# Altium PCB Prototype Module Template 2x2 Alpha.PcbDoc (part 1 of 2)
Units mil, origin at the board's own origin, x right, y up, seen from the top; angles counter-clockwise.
Board outline 1561.03 x 1620.2 mil, 6 copper layers (Component Side, Ground Plane (GND), Inner Layer 1, Inner Layer 2, Power Plane (VCC), Solder Side), stack 51.068 mil thick; 166 components, 80 nets, 785 pads, 445 vias.
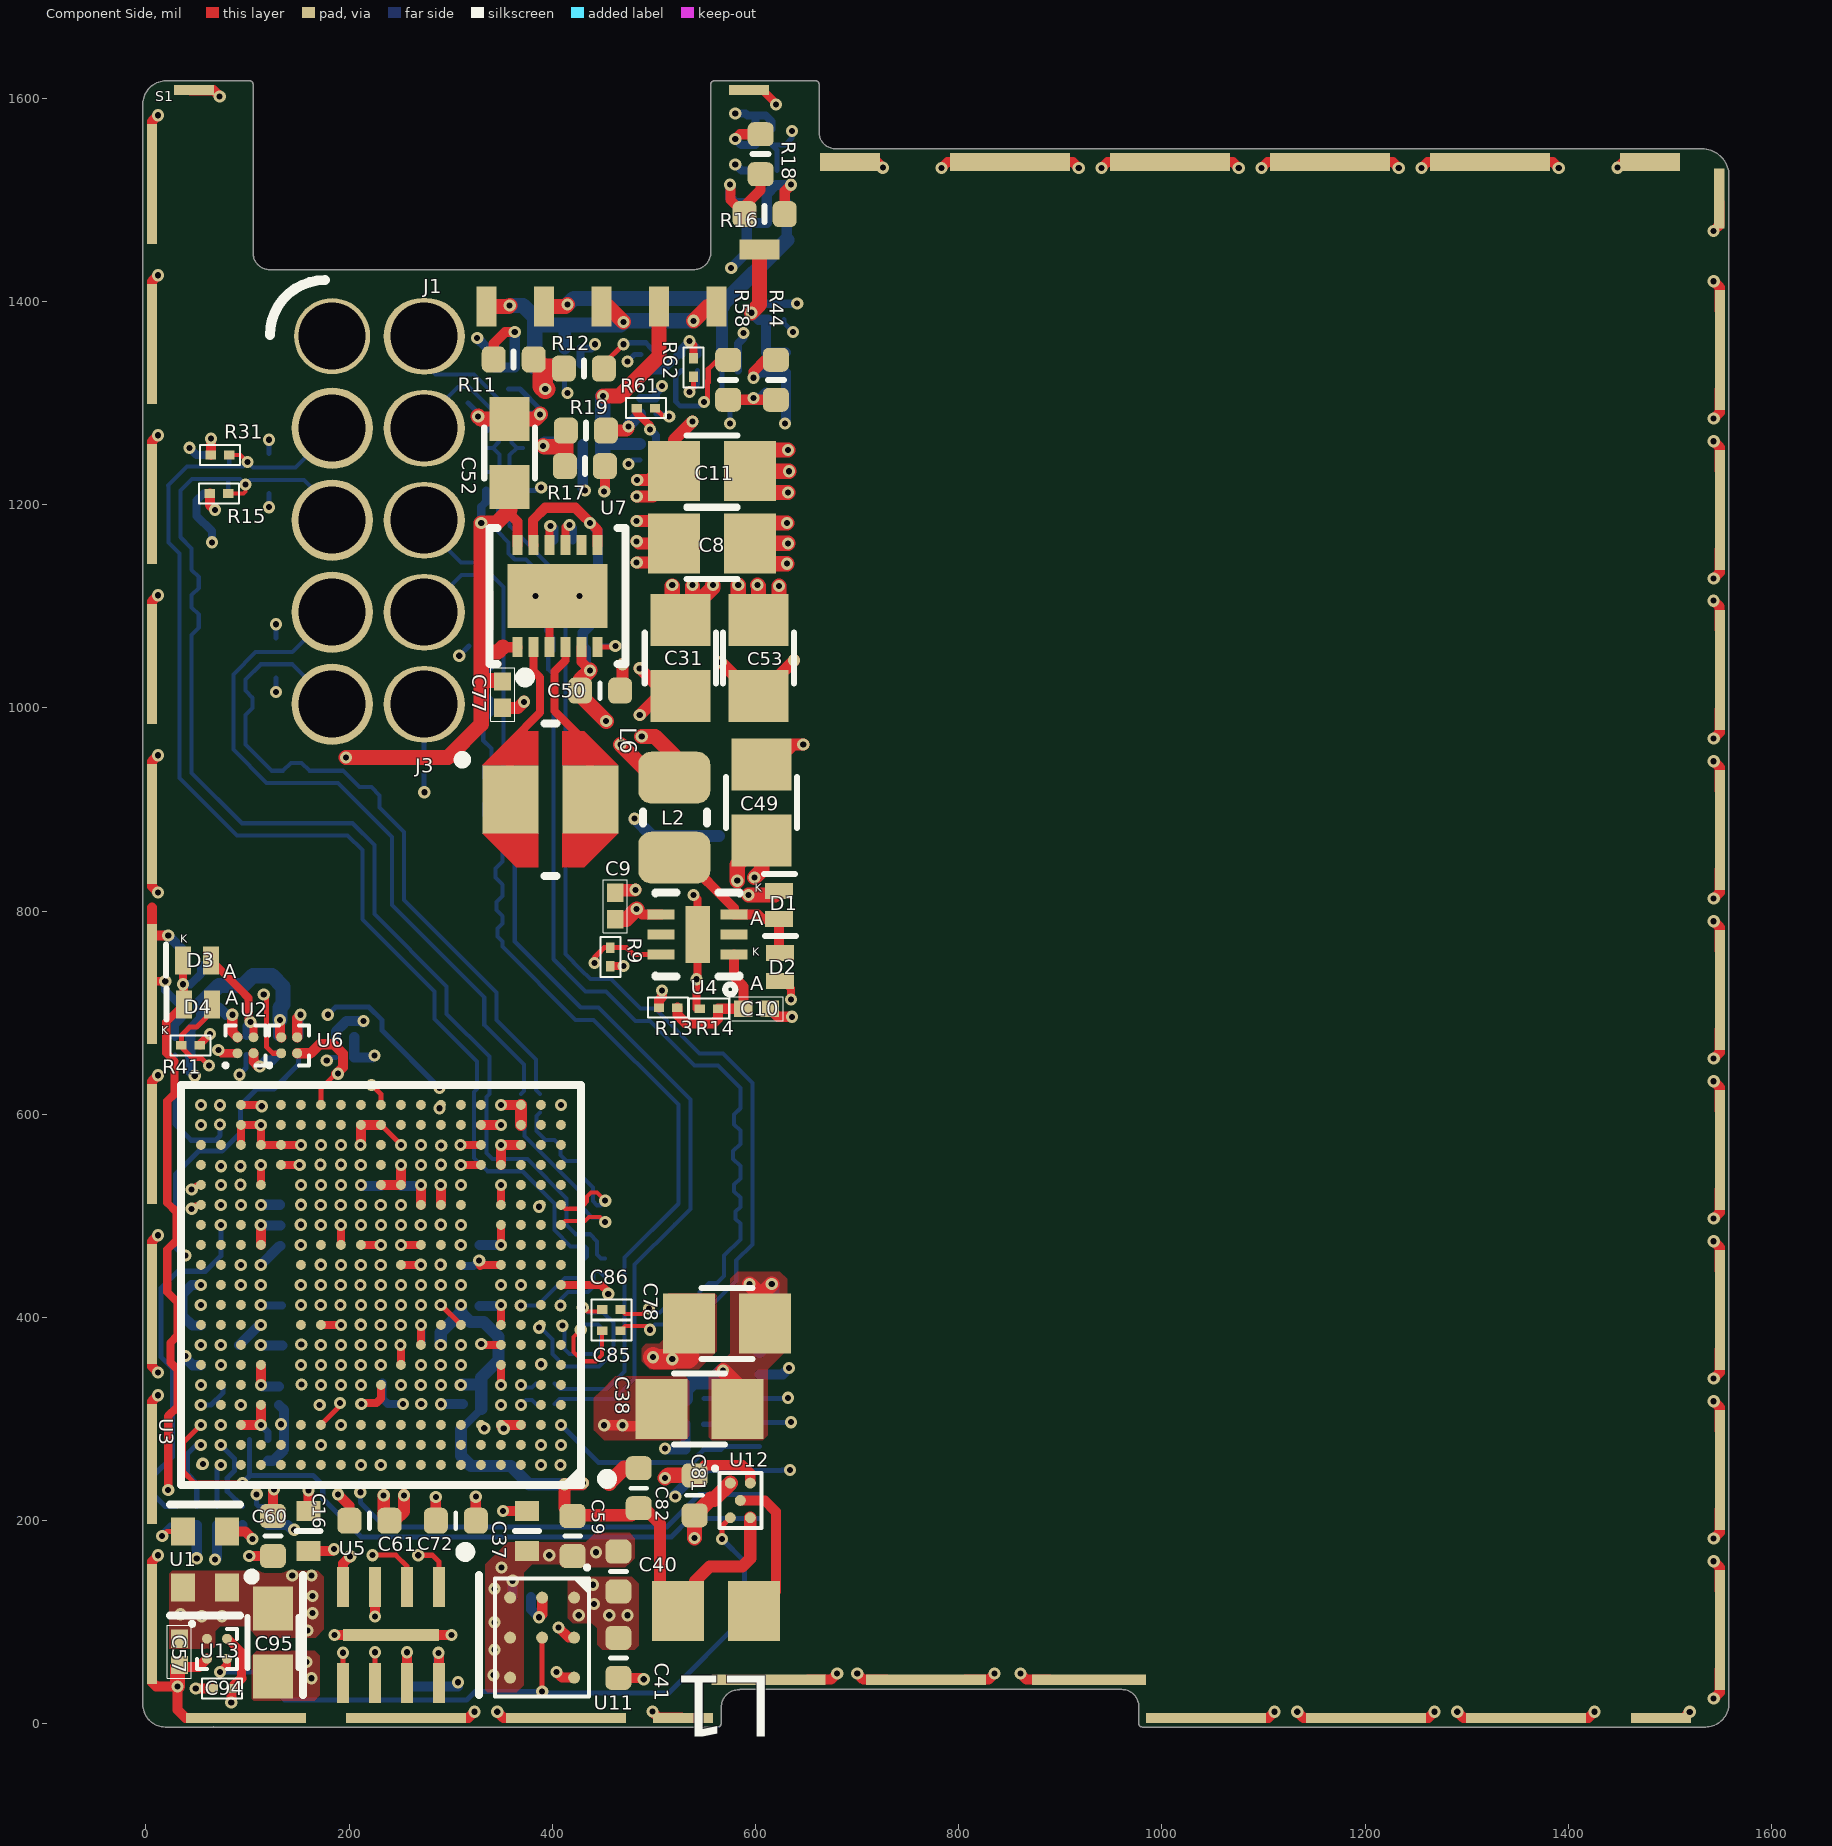
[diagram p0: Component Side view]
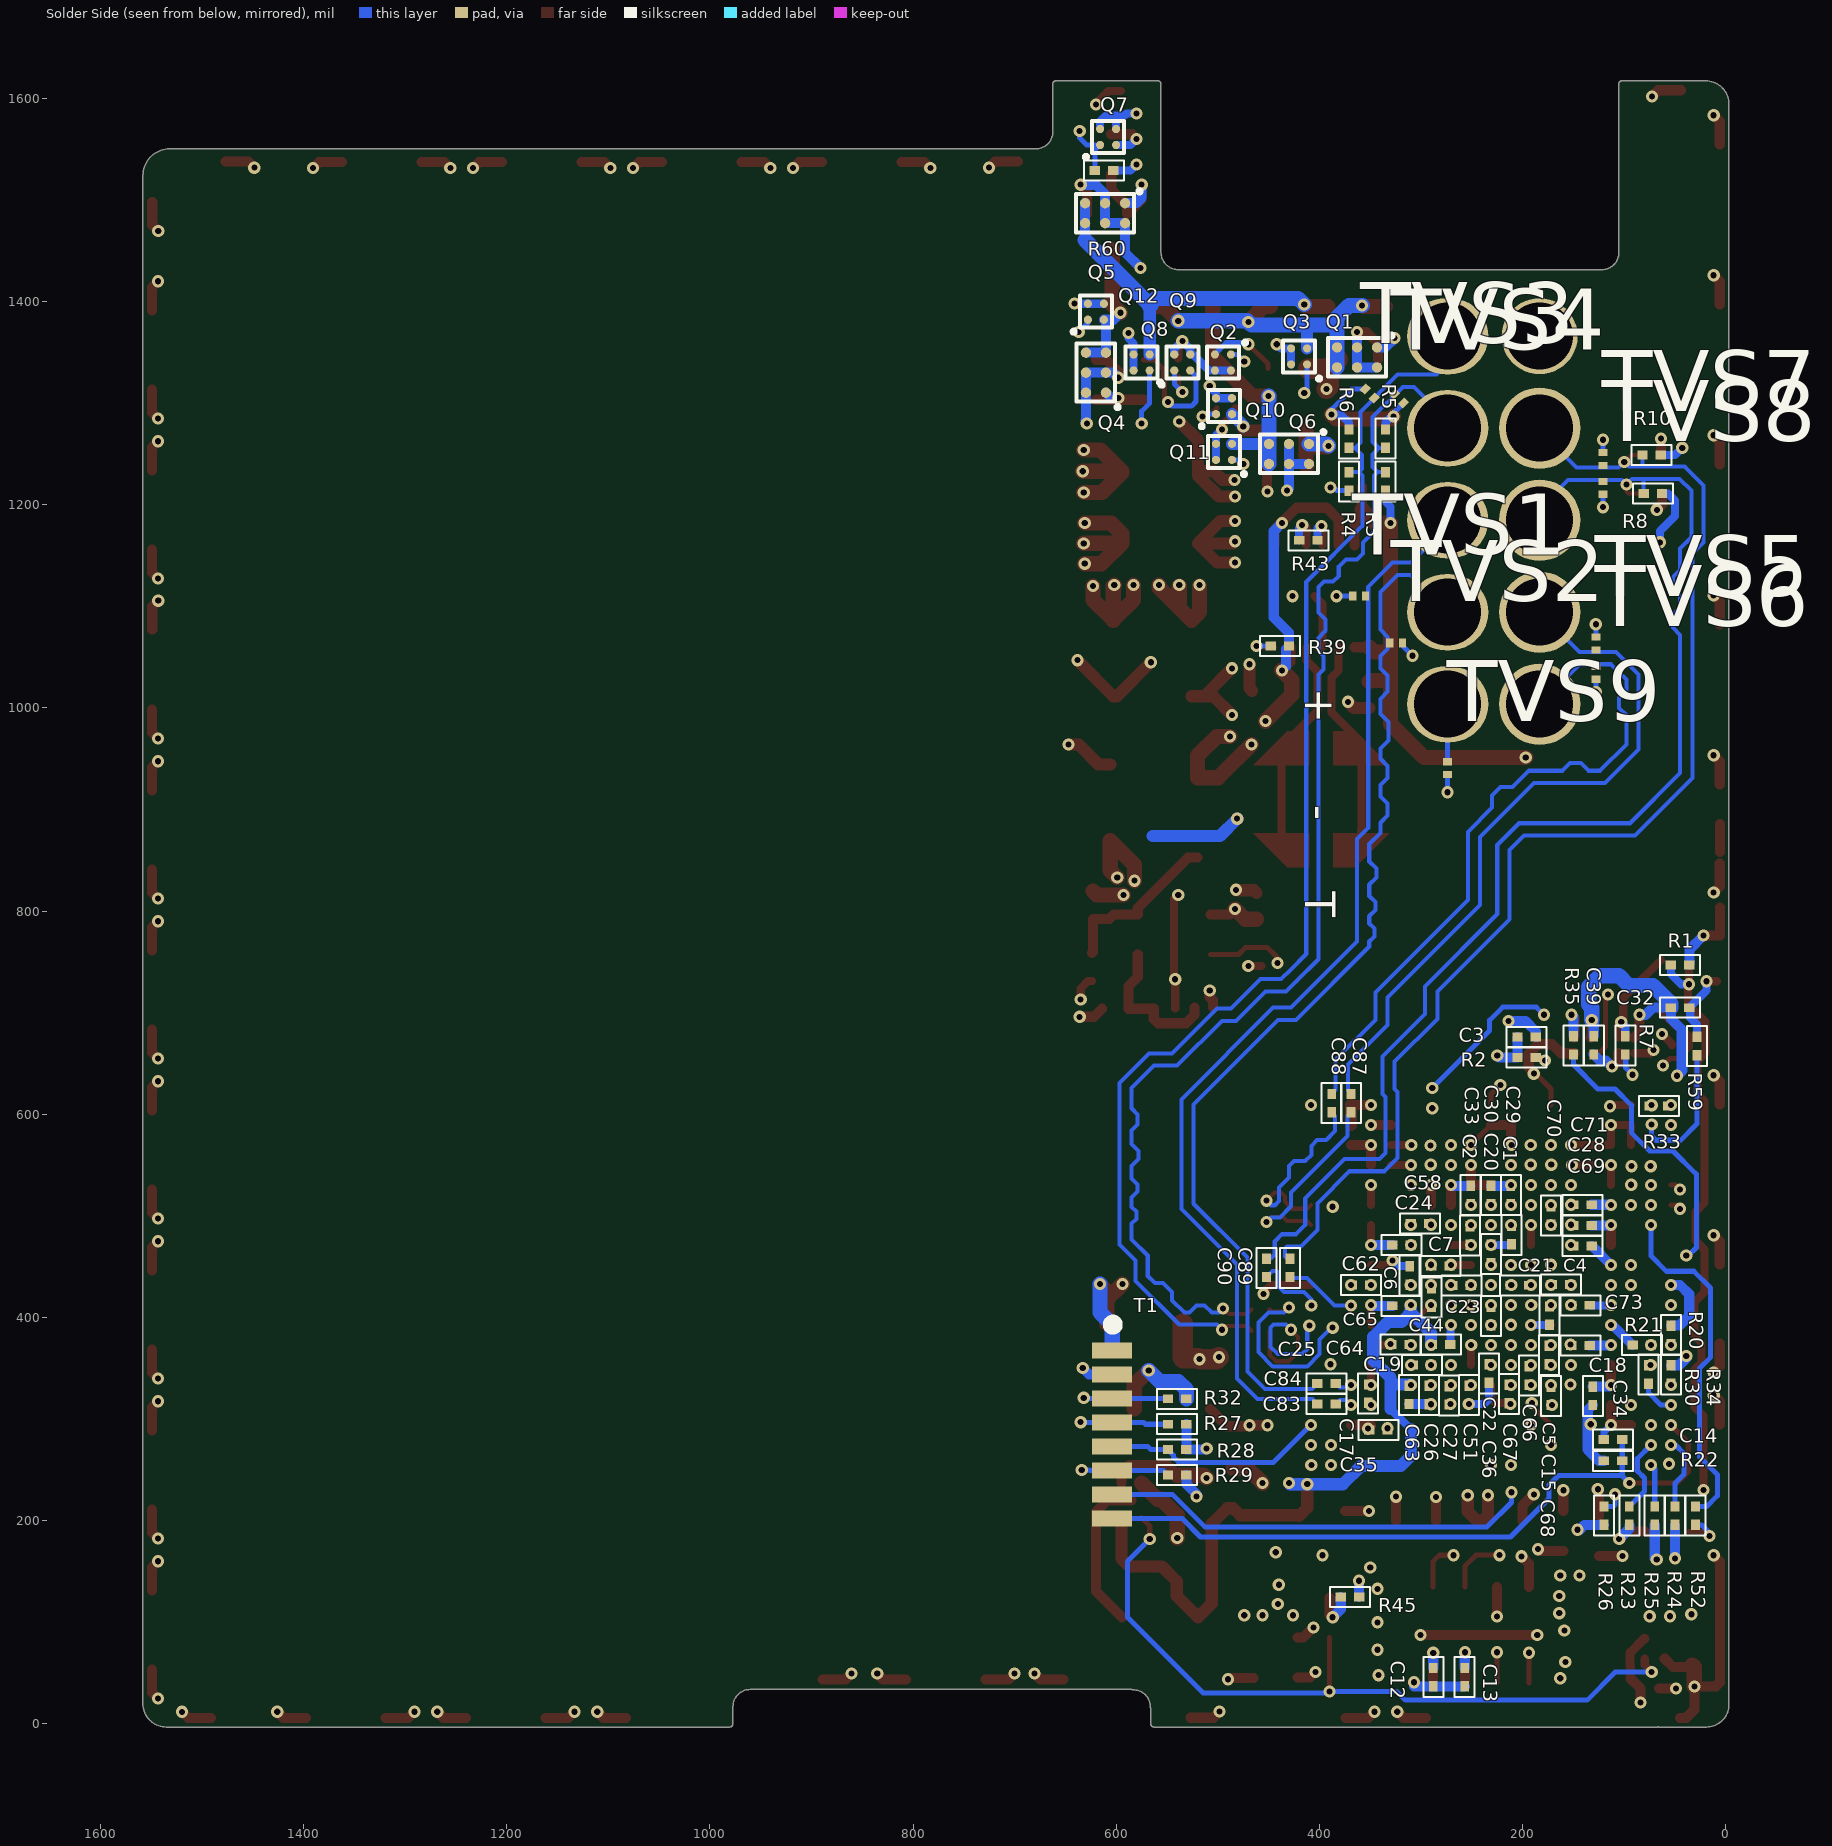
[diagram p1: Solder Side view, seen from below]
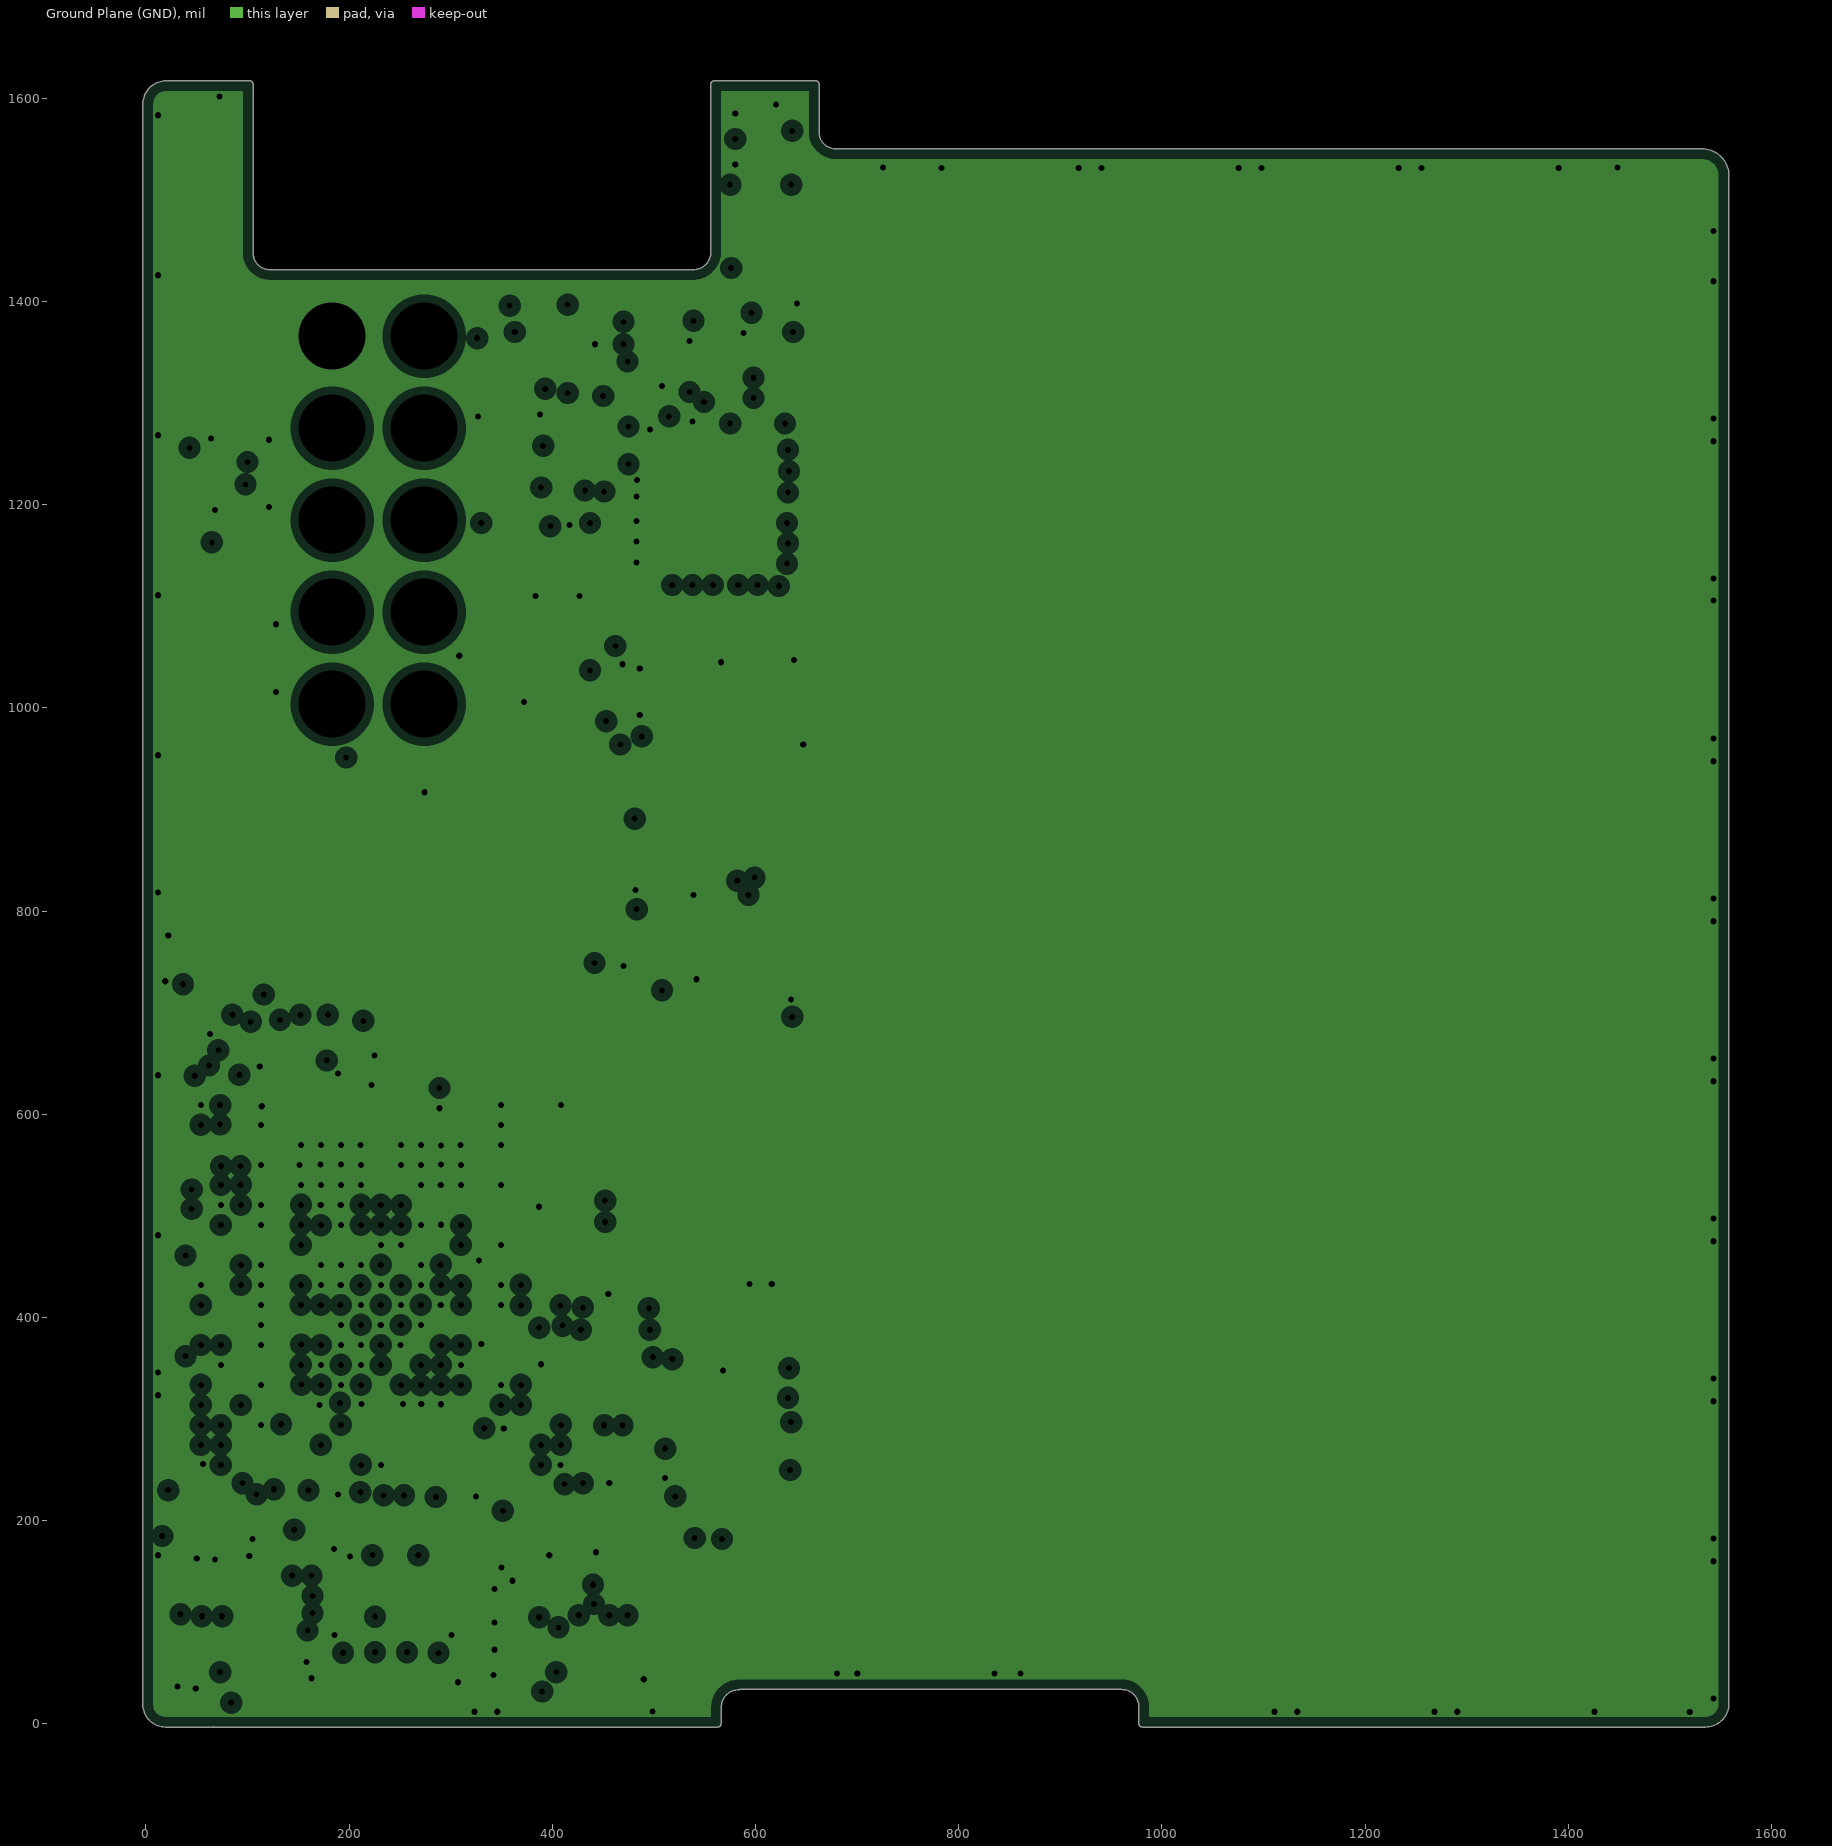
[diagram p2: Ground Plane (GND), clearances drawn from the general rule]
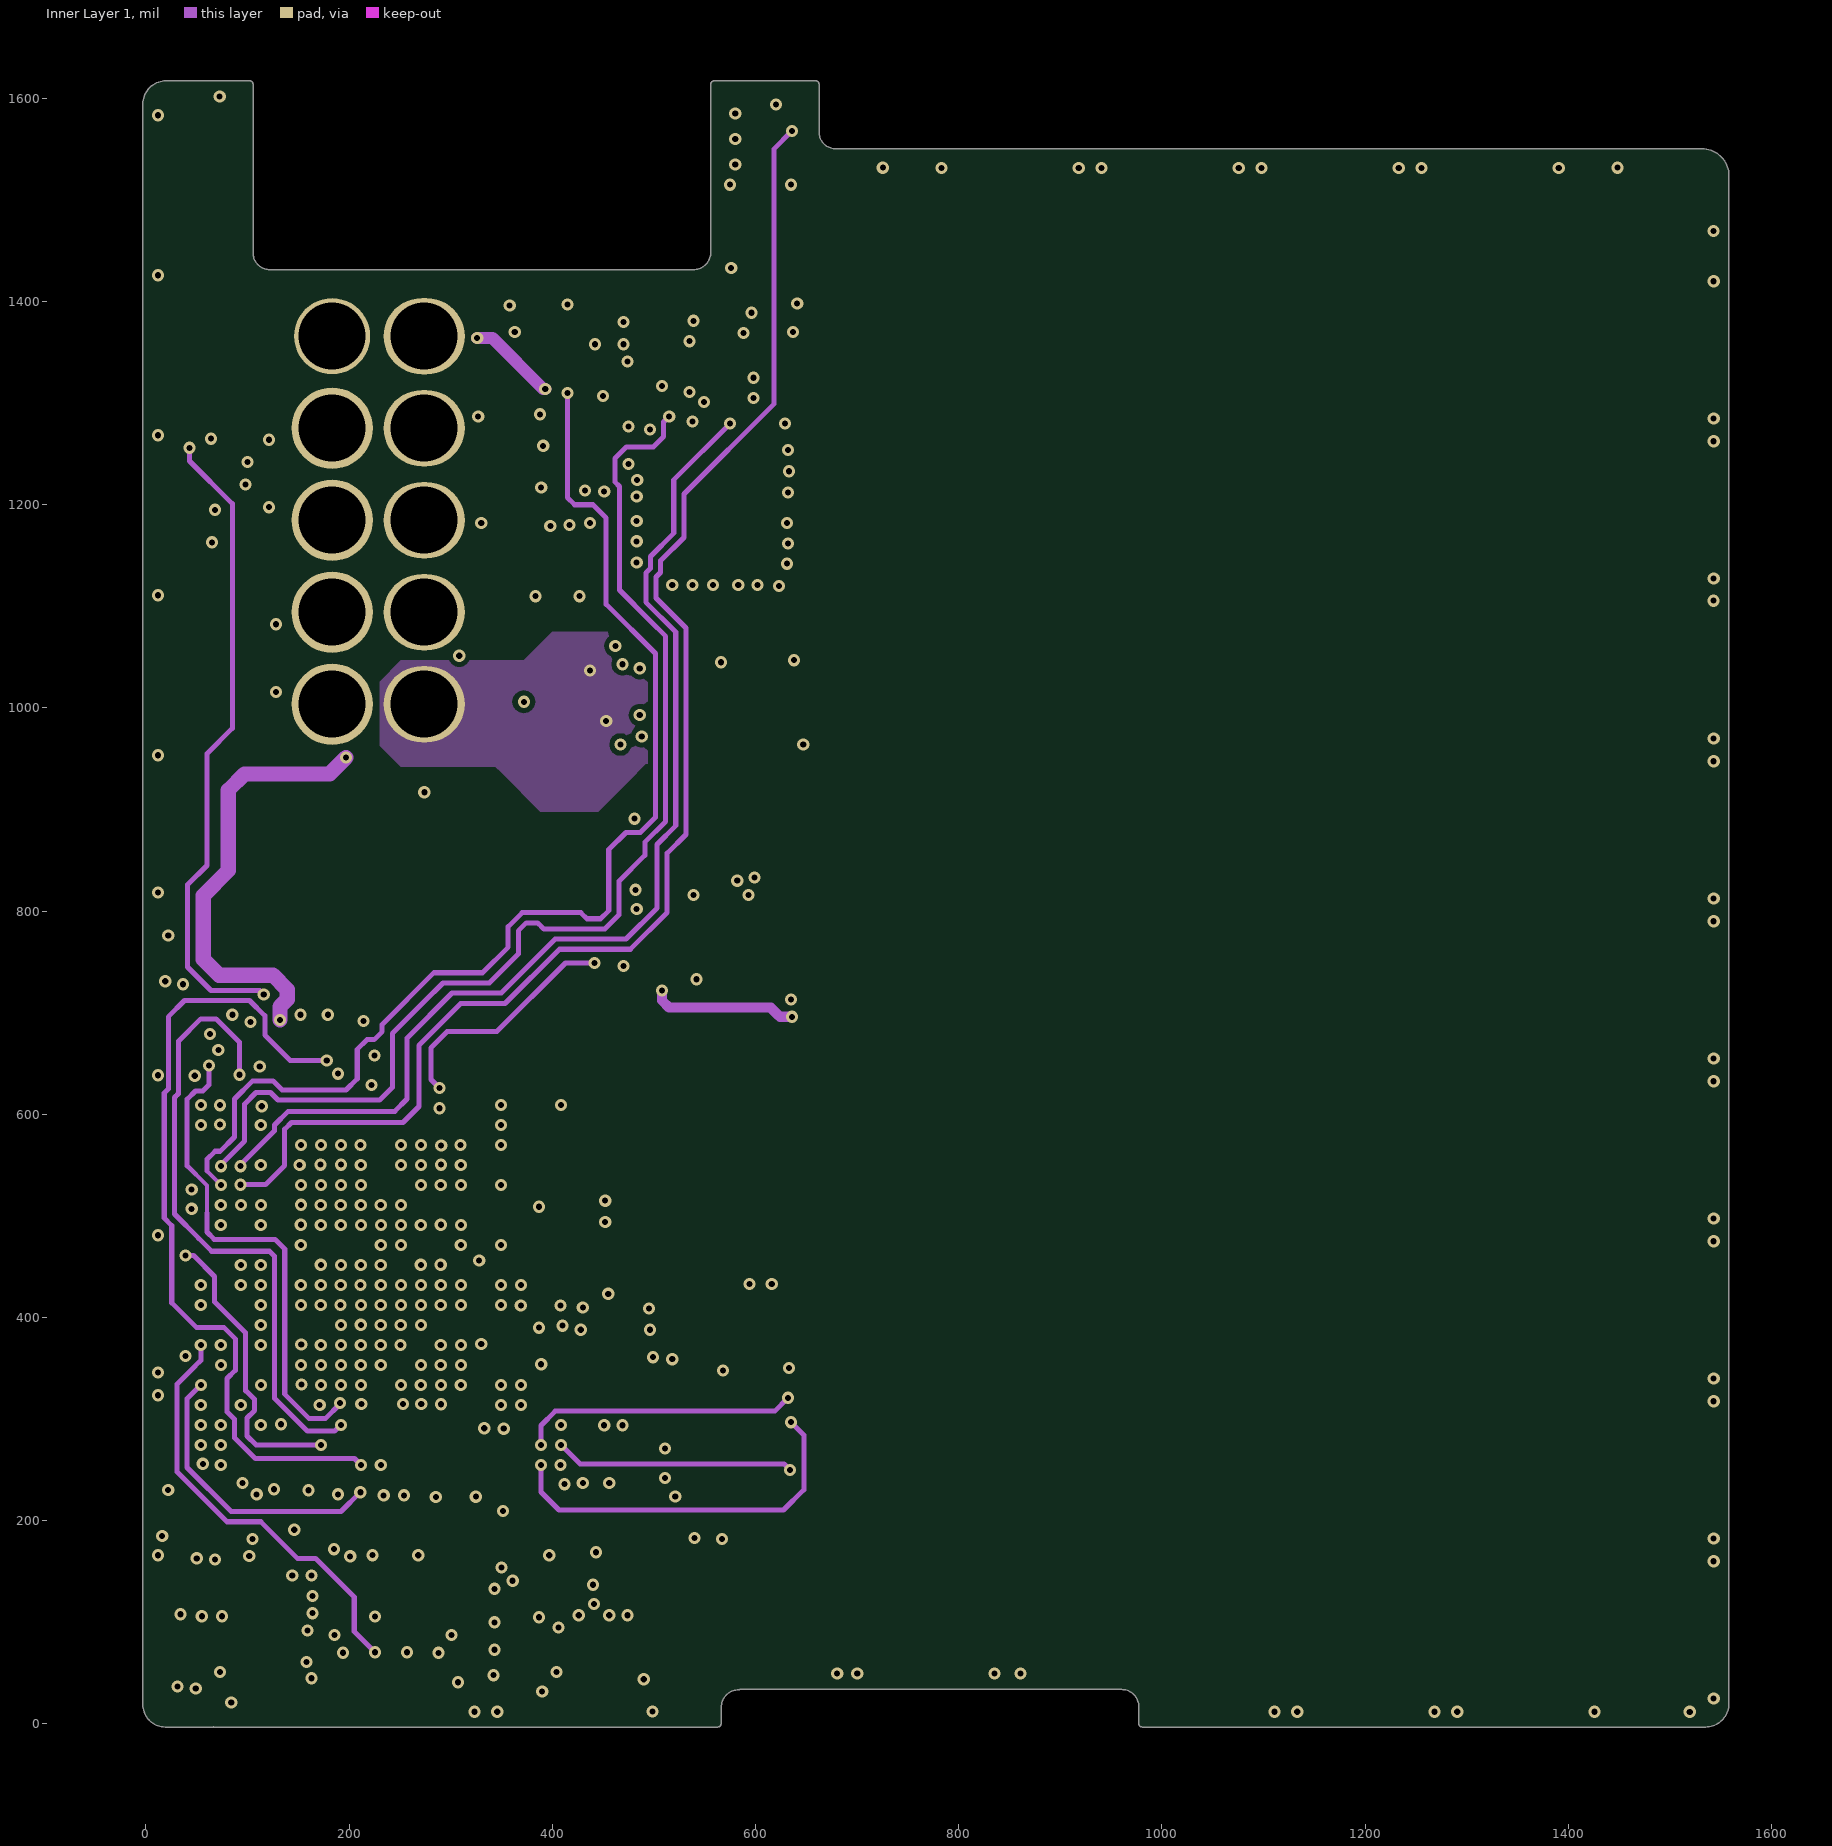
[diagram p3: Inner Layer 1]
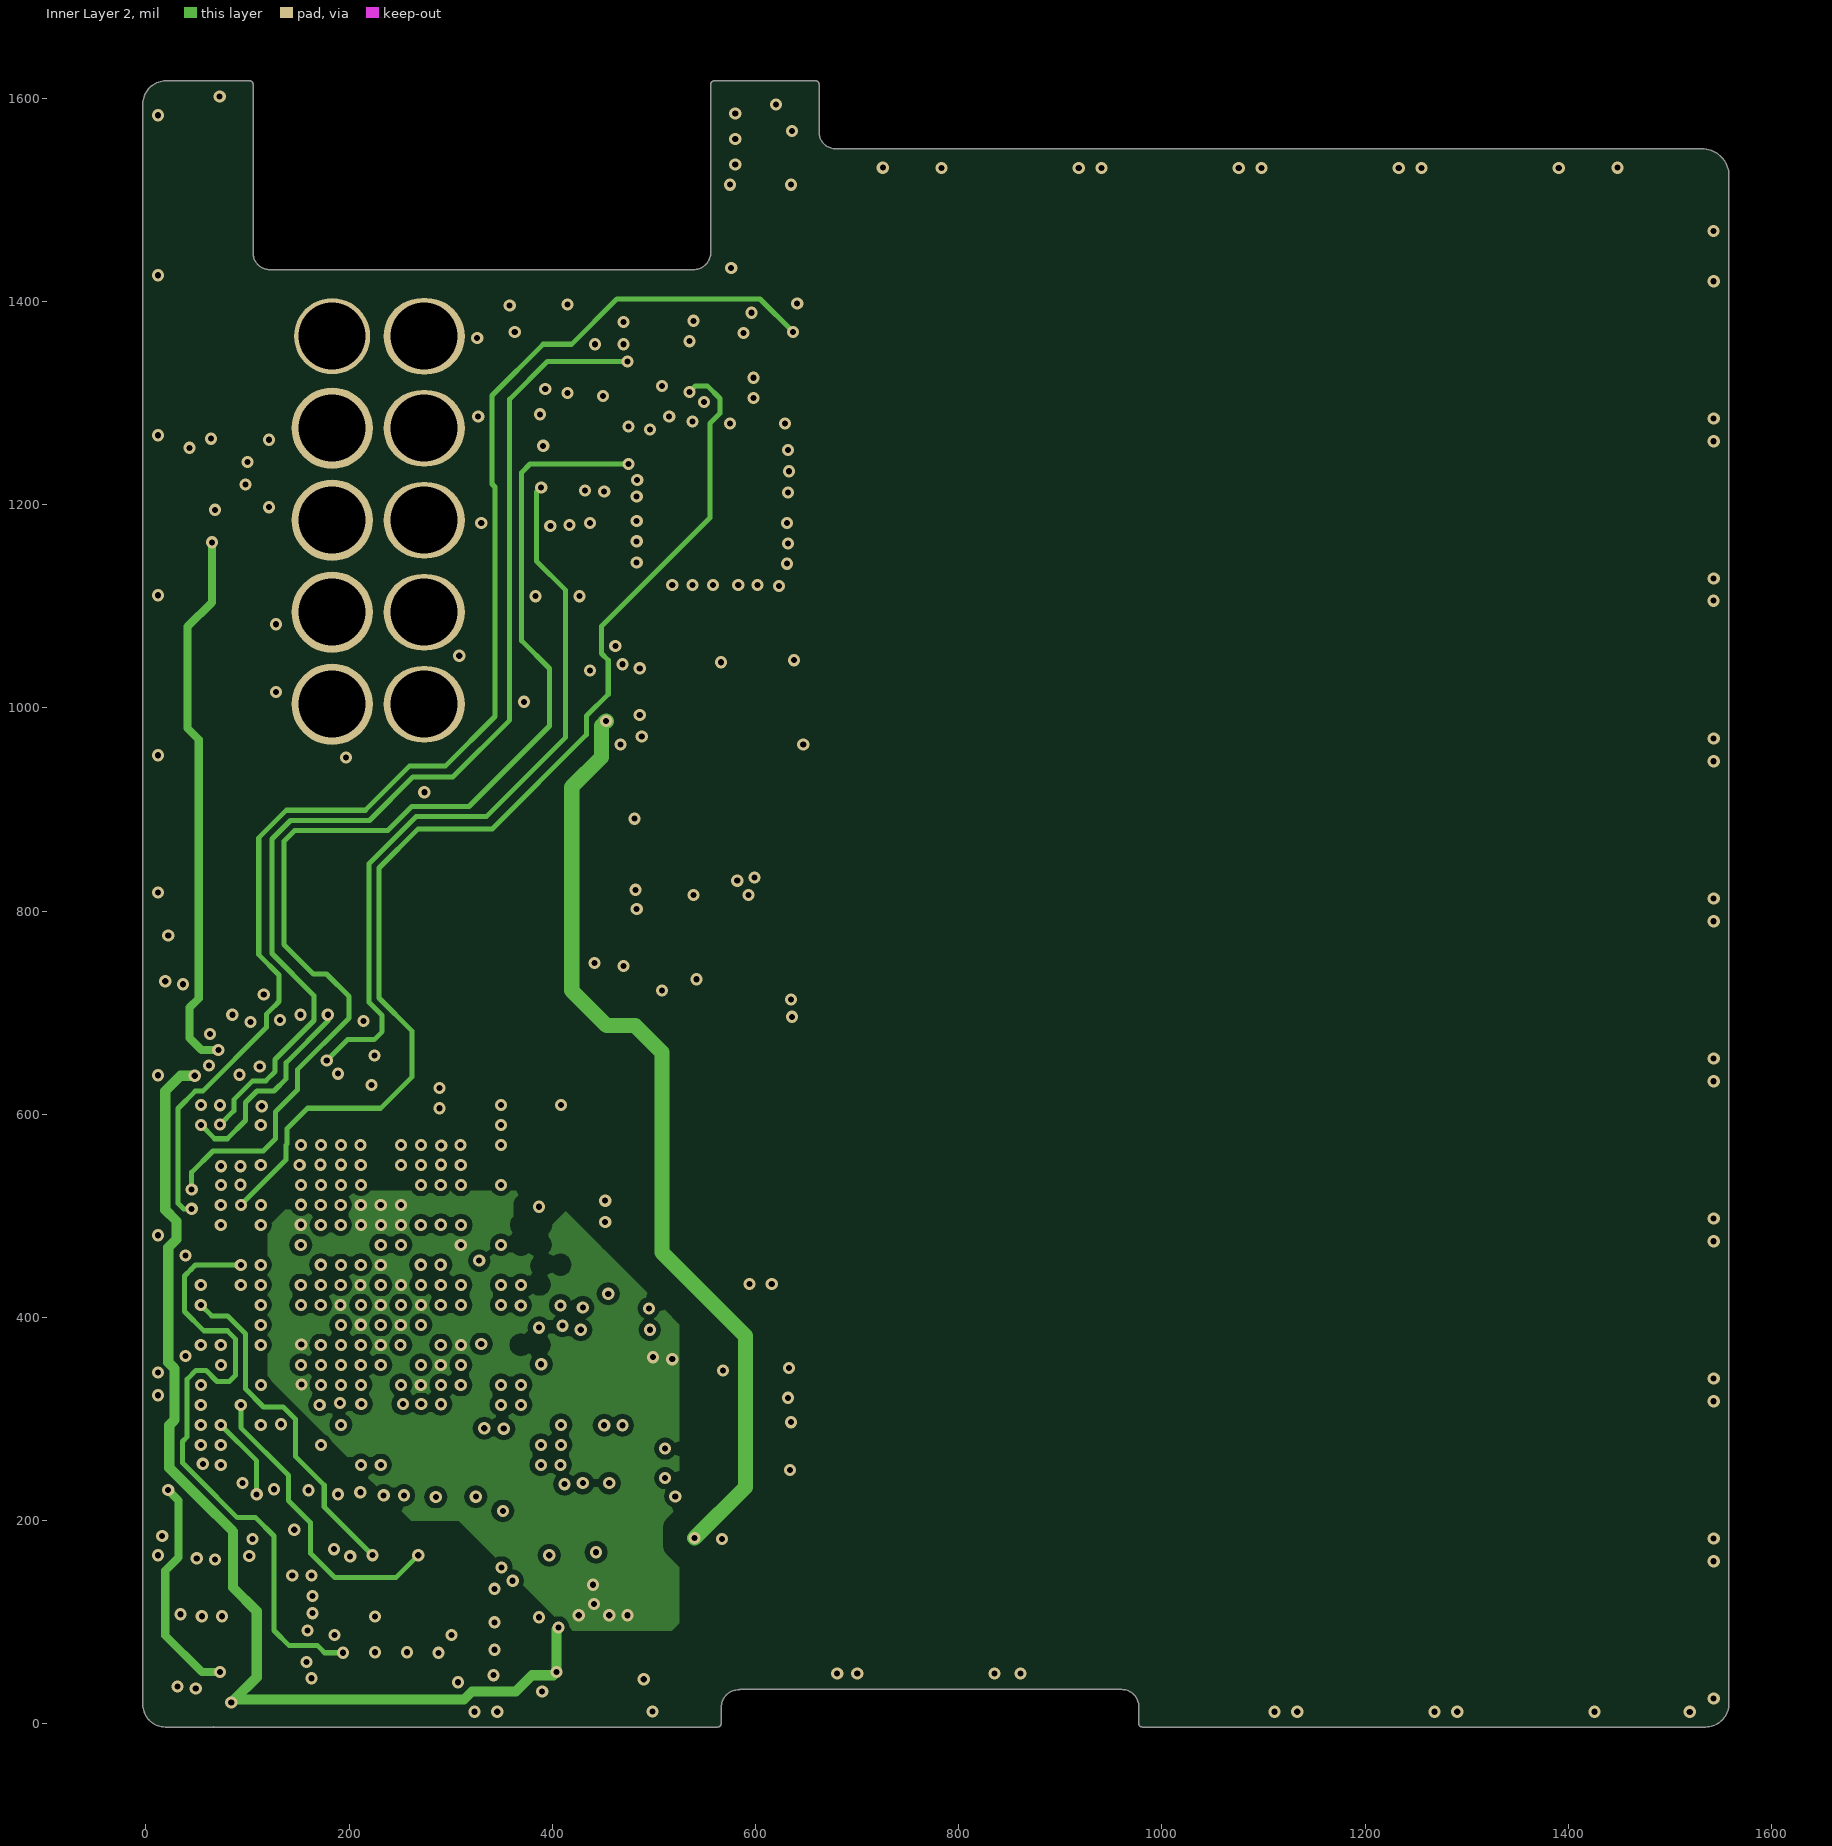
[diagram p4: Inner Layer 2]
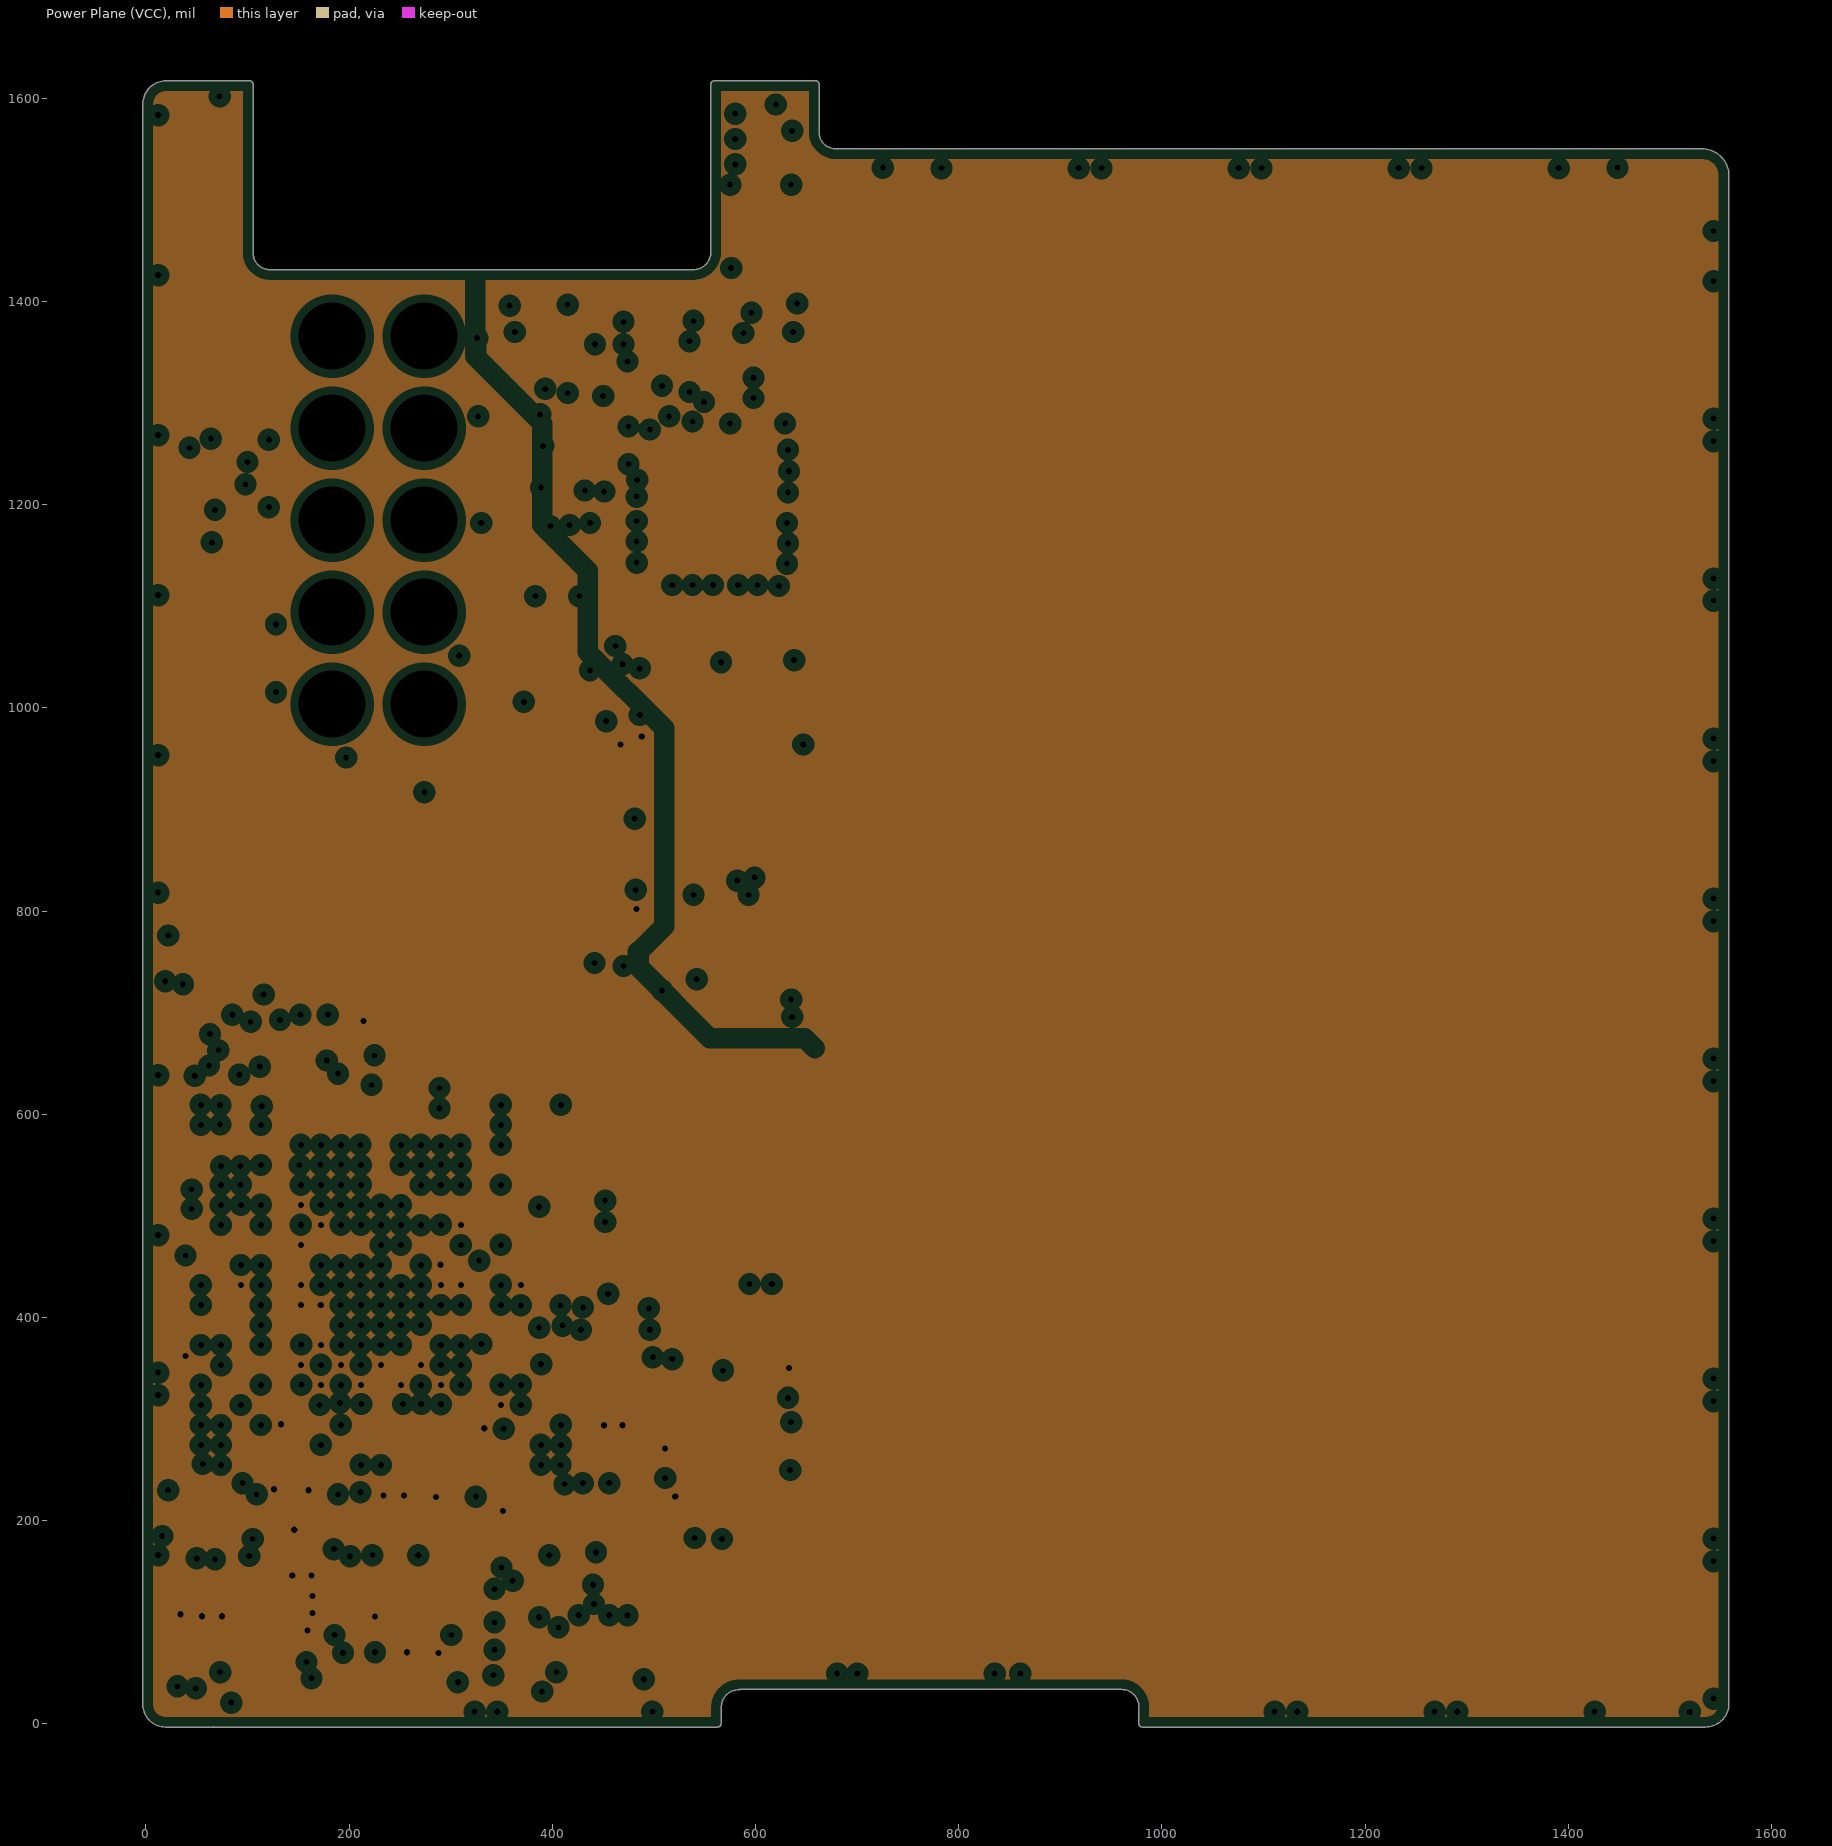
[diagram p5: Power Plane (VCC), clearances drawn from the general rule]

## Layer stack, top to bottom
Top Solder: solder mask 0.4, Solder Resist, Dk 3.5
Component Side: signal copper 1.4
Dielectric1: core 12.6, FR-4, Dk 4.8
Ground Plane (GND): plane copper 1.417, net GND
Dielectric4: prepreg 5, Dk 4.2
Inner Layer 1: signal copper 1.417
Dielectric2: core 10, Dk 4.2
Inner Layer 2: signal copper 1.417
Dielectric3: prepreg 5, Dk 4.2
Power Plane (VCC): plane copper 1.417, net (Multiple Nets)
Dielectric5: core 10, Dk 4.2
Solder Side: signal copper 1.4
Bottom Solder: solder mask 0.4, Solder Resist, Dk 3.5

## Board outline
19,-3.01 66,-3.01 ccw(c66,0) 66.5,-2.97 ccw(c67,0) 67,-3.01 562.99,-3.01 ccw(c562.99,0) 565.02,-2.23 ccw(c563,0.01) 566.02,0.01 566.02,15.19 ccw(c563.37,16.63) 566.38,16.63 cw(c583.37,16.63) 583.37,33.62 ccw(c583.37,36.63) 584.81,33.99 959.8,33.99 ccw(c960.28,36.96) 960.28,33.95 cw(c960.28,16.96) 977.26,16.96 ccw(c980.28,16.96) 977.3,16.48 977.3,0 ccw(c980.31,0) 980.39,-3.01 1535,-3.01 ccw(c1535,20) 1558.02,20 1558.02,1524 ccw(c1531.76,1524) 1531.76,1550.26 679.13,1550.26 cw(c679.13,1566.93) 662.46,1566.93 662.46,1614.17 ccw(c659.45,1614.17) 659.45,1617.19 559.05,1617.19 ccw(c559.05,1614.17) 556.9,1616.28 ccw(c559,1614.12) 555.99,1614.12 555.99,1448.61 cw(c538.74,1448.61) 538.74,1431.36 122.05,1431.36 cw(c122.05,1448.03) 105.38,1448.03 105.38,1614.17 ccw(c102.36,1614.17) 102.36,1617.19 19.68,1617.19 ccw(c19.68,1594.49) -3.01,1594.49 -3.01,19 ccw(c19,19)

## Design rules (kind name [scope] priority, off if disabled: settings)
Clearance diff_1 [InNetClass('diff')] p1: gap=5
Clearance [All] p2: gap=5
DiffPairsRouting [All] p1: maxlimit=8 minlimit=8 mostfreqgap=8 toplayer_minwidth=15 toplayer_maxwidth=15 toplayer_prefwidth=15 midlayer1_minwidth=15 midlayer1_maxwidth=15 midlayer1_prefwidth=15 midlayer2_minwidth=15 midlayer2_maxwidth=15 midlayer2_prefwidth=15 bottomlayer_minwidth=15 bottomlayer_maxwidth=15 bottomlayer_prefwidth=15 maxuncoupledlength=500
FabricationTestPointUsage [All] p1 off: valid=0 allowmultiple=FALSE
FabricationTestpoint [(IsPad And (OnTopLayer Or OnBottomLayer))] p1 off: side=3 testpointundercomponent=TRUE minsize=40 maxsize=100 preferedsize=60 minholesize=0 maxholesize=40 preferedholesize=32 testpointgrid=1 allowsidetop=TRUE allowsidebottom=TRUE usegrid=TRUE gridtolerance=0.01
MatchedLengths DiffPair_MatchedLengths [InDifferentialPair ('SERDES_TX_CHIP')] p1: tolerance=1000 checknetsindiffpair=TRUE checkdiffpairvsdiffpair=TRUE checkothers=TRUE
MatchedLengths DiffPair_MatchedLengths_1 [InDifferentialPair ('SERDES_TX')] p2: tolerance=1000 checknetsindiffpair=TRUE checkdiffpairvsdiffpair=TRUE checkothers=TRUE
MatchedLengths DiffPair_MatchedLengths_2 [InDifferentialPair ('SERDES_RX')] p3: tolerance=1000 checknetsindiffpair=TRUE checkdiffpairvsdiffpair=TRUE checkothers=TRUE
MatchedLengths DiffPair_MatchedLengths_3 [InDifferentialPair ('RCLK_100MHZ')] p4: tolerance=1000 checknetsindiffpair=TRUE checkdiffpairvsdiffpair=TRUE checkothers=TRUE
MatchedLengths DiffPair_MatchedLengths_4 [InDifferentialPair ('OSC_100MHZ')] p5: tolerance=1000 checknetsindiffpair=TRUE checkdiffpairvsdiffpair=TRUE checkothers=TRUE
MinimumSolderMaskSliver [All] p1: minsoldermaskwidth=3
PlaneClearance [All] p1: clearance=8
PlaneConnect [All] p1: planeconnectstyle=Direct reliefexpansion=8 reliefentries=4 reliefconductorwidth=8 reliefairgap=8
PolygonConnect [All] p1: connectstyle=Direct reliefconductorwidth=10 reliefentries=4 polygonreliefangle="90 Angle" airgapwidth=10
RoutingVias [All] p1: holewidth=6 width=12 viastyle="Through Hole" minholewidth=6 minwidth=12 maxholewidth=6 maxwidth=12
SilkToSilkClearance [All] p1: silktosilkclearance=3
SilkToSolderMaskClearance [IsPad] p1: minsilkscreentomaskgap=3 clearancetoexposedcopper=TRUE
SolderMaskExpansion [All] p1: expansion=4
Width diff [InNetClass('diff')] p1: maxlimit=4 minlimit=4 preferedwidth=4
Width [All] p2: maxlimit=30 minlimit=4 preferedwidth=5
21 further rules are at their usual default settings.

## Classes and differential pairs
differential pair TX: +TX_P -TX_N
differential pair TX_CLK: +TX_CLK_P -TX_CLK_N
differential pair RX: +RX_P -RX_N
differential pair RX_CLK: +RX_CLK_P -RX_CLK_N
differential pair C_TX: +C_TX_P -C_TX_N
differential pair C_TX_CLK: +C_TX_CLK_P -C_TX_CLK_N
differential pair C_RX: +C_RX_P -C_RX_N
differential pair C_RX_CLK: +C_RX_CLK_P -C_RX_CLK_N

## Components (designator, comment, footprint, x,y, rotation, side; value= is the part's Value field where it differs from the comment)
C1 "0.1uF" C_01005 211,481 r90 bottom
C2 "0.1uF" C_01005 251.97,480.71 r90 bottom
C3 "0.1uF" C_01005 196,676 r180 bottom
C4 "0.1uF" C_01005 162.17,432.52 r180 bottom
C5 "0.1uF" C_01005 173.69,401.76 r90 bottom
C6 "0.1uF" C_01005 311.17,441.52 r270 bottom
C7 "0.1uF" C_01005 281.1,450.79 r0 bottom locked
C8 "22µF" C_ERA-0805#1 557,1162 r0 top
C9 "0.1UF" CAPC0201 462,805 r270 top
C10 "C_0201_22pF" CAPC0201 601,704 r0 top
C11 "22µF" C_ERA-0805#1 557,1233 r0 top
C12 "0.1uF" C_01005 288,46 r270 bottom
C13 "0.1uF" C_01005 257,46 r270 bottom
C14 "0.1uF" C_01005 111,280 r0 bottom
C15 "0.1uF" C_01005 174,363 r270 bottom
C16 "1.0uF" C_ERA-0402 160,190 r90 top
C17 "0.1uF" C_01005 352,325 r90 bottom
C18 "0.1uF" C_01005 143.17,372.52 r0 bottom
C19 "0.1uF" C_01005 299.24,353.35 r180 bottom
C20 "0.1uF" C_01005 231.17,462.52 r270 bottom
C21 "0.1uF" C_01005 202.69,431.76 r0 bottom
C22 "0.1uF" C_01005 231.17,401.52 r90 bottom
C23 "0.1uF" C_01005 260.17,431.52 r180 bottom
C24 "0.1uF" C_01005 319.17,471.52 r180 bottom
C25 "0.1uF" C_01005 320.17,373.52 r180 bottom
C26 "0.1uF" C_01005 292.32,323.68 r90 bottom
C27 "0.1uF" C_01005 272.55,323.43 r90 bottom
C28 "0.1uF" C_01005 141.17,490.52 r0 bottom
C29 "0.1uF" C_01005 211.67,520.52 r270 bottom
C30 "0.1uF" C_01005 231.17,520.52 r270 bottom
C31 "22µF" C_ERA-0805#1 526,1049 r90 top
C32 "0.1uF" C_01005 45,705 r0 bottom
C33 "0.1uF" C_01005 251.17,520.52 r270 bottom
C34 "0.1uF" C_01005 131,323 r270 bottom
C35 "0.1uF" C_01005 342.1,289.3 r180 bottom
C36 "0.1uF" C_01005 233,345 r90 bottom
C37 "1.0uF" C_ERA-0402 375,190 r90 top
C38 "22uF" C_ERA-0805#1 545,310 r180 top
C39 "0.1uF" C_01005 130,668 r90 bottom
C40 "10uF" C_0402 465,150 r270 top
C41 "1uF" C_0402 465,65 r90 top
C44 "0.1uF" C_01005 289.69,419.76 r90 bottom
C49 "22µF" C_ERA-0805#1 606,907 r270 top
C50 "10uF" C_0402 447,1017 r180 top
C51 "0.1uF" C_01005 253,324 r90 bottom
C52 "22uF" C_ERA-0603 358,1251 r270 top
C53 "22µF" C_ERA-0805#1 603,1049 r90 top
C57 "0.47µF" CAPC0201 33,71 r90 top
C58 "0.1uF" C_01005 301.17,492.52 r0 bottom
C59 "10uF" C_0402 420,185 r90 top
C60 "10uF" C_0402 125,185 r90 top
C61 "10uF" C_0402 220,200 r0 top
C62 "0.1uF" C_01005 359,432 r0 bottom
C63 "0.1uF" C_01005 312,324 r90 bottom
C64 "0.1uF" C_01005 280.17,373.52 r0 bottom
C65 "0.1uF" C_01005 319.17,411.52 r180 bottom
C66 "0.1uF" C_01005 194,343 r90 bottom
C67 "0.1uF" C_01005 213.58,324.69 r90 bottom
C68 "0.1uF" C_01005 172,323 r90 bottom
C69 "0.1uF" C_01005 141.17,470.52 r0 bottom
C70 "0.1uF" C_01005 172.17,500.52 r270 bottom
C71 "0.1uF" C_01005 141,511 r0 bottom
C72 "10uF" C_0402 305,200 r180 top
C73 "0.1uF" C_01005 143,412 r0 bottom
C77 "0.47µF" CAPC0201 351,1013 r90 top
C78 "22uF" C_ERA-0805#1 572,394 r180 top
C81 "4.7uF" C_0402 540,225 r270 top
C82 "10uF" C_0402 485,232 r270 top
C83 "0.1uF" C_01005 393,315 r180 bottom
C84 "0.1uF" C_01005 393,335 r180 bottom
C85 "0.1uF" C_01005 458,387 r180 top
C86 "0.1uF" C_01005 458,408 r180 top
C87 "0.1uF" C_01005 369,611 r270 bottom
C88 "0.1uF" C_01005 388,611 r270 bottom
C89 "0.1uF" C_01005 429,449 r270 bottom
C90 "0.1uF" C_01005 452,449 r270 bottom
C94 "0.1uF" C_01005 75,35 r0 top
C95 "22uF" C_ERA-0603 125,80 r90 top
D1 "SBR0240LP-7" 2-XFDFN 623,806 r270 top
D2 "SBR0240LP-7" 2-XFDFN 624,745 r270 top
D3 "SBR0240LP-7" 2-XFDFN 50.2,751.61 r0 top
D4 "SBR0240LP-7" 2-XFDFN 51,708 r0 top
J1 "EPM" EPM_3X_CONNECTION 335,1395 r90 top
J3 "SPRING PIN" "10PIN SMD CONNECTOR" 273.86,1003.7 r90 top locked
L1 "2.2uH" C_ERA-0805#2 561,111 r180 top
L2 "CBC2016T220K" L_0806 520,892 r90 top
L6 "2.2uH Wirewound" L_SMD_2.2uH 398,910 r180 top
Q1 "SI8497DB-T2-E1" BGA6C50P3X2_145X96X59 363,1345 r0 bottom
Q2 "SI8808DB-T2-E1" BGA4C40P2X2_80X80X40 495,1340 r0 bottom
Q3 "SI8808DB-T2-E1" BGA4C40P2X2_80X80X40 420,1346 r90 bottom
Q4 "SI8497DB-T2-E1" BGA6C50P3X2_145X96X59 620,1330 r90 bottom
Q5 "SI8497DB-T2-E1" BGA6C50P3X2_145X96X59 611,1487 r0 bottom
Q6 "SI8497DB-T2-E1" BGA6C50P3X2_145X96X59 430,1250 r0 bottom
Q7 "SI8808DB-T2-E1" BGA4C40P2X2_80X80X40 608,1562 r180 bottom
Q8 "SI8808DB-T2-E1" BGA4C40P2X2_80X80X40 575,1340 r90 bottom
Q9 "SI8808DB-T2-E1" BGA4C40P2X2_80X80X40 535,1340 r180 bottom
Q10 "SI8808DB-T2-E1" BGA4C40P2X2_80X80X40 494,1297 r180 bottom
Q11 "SI8808DB-T2-E1" BGA4C40P2X2_80X80X40 494,1252 r90 bottom
Q12 "SI8808DB-T2-E1" BGA4C40P2X2_80X80X40 620,1390 r180 bottom
R1 "1M Ohms" R_01005 45,747 r180 bottom
R2 "1k" R_01005 196,656 r180 bottom
R3 "10K" R_01005 335,1223 r270 bottom
R4 "10K" R_01005 371,1223 r270 bottom
R5 "1M Ohms" R_01005 335,1265 r90 bottom
R6 "1M Ohms" R_01005 371,1265 r90 bottom
R7 "10K" R_01005 99,668 r270 bottom
R8 "10K" R_01005 71.94,1211 r180 bottom
R9 "1k" R_01005 457,755 r270 top
R10 "10K" R_01005 72.94,1249 r180 bottom
R11 "100" R_0402 362,1343 r0 top
R12 "270" R_0402 431,1334 r0 top
R13 "10K" R_01005 514,705 r0 top
R14 "4.7k" R_01005 554,704 r180 top
R15 "1M Ohms" R_01005 71.94,1211 r180 top
R16 "100" R_0402 609,1486 r180 top
R17 "100" R_0402 432,1238 r180 top
R18 "270" R_0402 605,1545 r90 top
R19 "270" R_0402 433,1273 r0 top
R20 "1k" R_01005 54,383 r270 bottom
R21 "1k" R_01005 82.76,373.03 r0 bottom
R22 "10K" R_01005 111,259 r180 bottom
R23 "10K" R_01005 95,205 r270 bottom
R24 "10K" R_01005 50,205 r270 bottom
R25 "10K" R_01005 70,205 r270 bottom
R26 "10K" R_01005 120,205 r270 bottom
R27 "4.7k" R_01005 540,295 r0 bottom
R28 "4.7k" R_01005 540,270 r0 bottom
R29 "4.7k" R_01005 540,245 r0 bottom
R30 "10K" R_01005 76,344 r90 bottom
R31 "1M Ohms" R_01005 72.94,1249 r180 top
R32 "4.7k" R_01005 540,320 r180 bottom
R33 "10K" R_01005 65.91,608.35 r180 bottom
R34 "10K" R_01005 54,344 r90 bottom
R35 "10K" R_01005 150,668 r270 bottom
R39 "10K" R_01005 439,1061 r0 bottom
R41 "10K" R_01005 44,668 r180 top
R43 "10K" R_01005 411,1165 r180 bottom
R44 "100" R_0402 620,1323 r270 top
R45 "10K" R_01005 370,125 r0 bottom
R52 "33" R_01005 30,205 r90 bottom
R58 "270" R_0402 573,1323 r90 top
R59 "1k" R_01005 28.54,667.32 r90 bottom
R60 "1k" R_01005 612,1529 r180 bottom
R61 "1k" R_01005 492,1295 r180 top
R62 "1k" R_01005 539,1335 r90 top
S1 "RFSHIELD" RFSHIELD_2X2_MODULE 0,0 r0 top locked
T1 "8 PIN TEST_INTERFACE" "8-PIN TEST INTERFACE" 604,285 r180 bottom
TVS1 "TVS_ESDAVLC6-1BV2" ST_MICRO_TVS 361,1110 r0 bottom
TVS2 "TVS_ESDAVLC6-1BV2" ST_MICRO_TVS 324.61,1064 r180 bottom
TVS3 "TVS_ESDAVLC6-1BV2" ST_MICRO_TVS 350.55,1309.55 r45 bottom
TVS4 "TVS_ESDAVLC6-1BV2" ST_MICRO_TVS 321.64,1304.64 r225 bottom
TVS5 "TVS_ESDAVLC6-1BV2" ST_MICRO_TVS 128,1063.39 r90 bottom
TVS6 "TVS_ESDAVLC6-1BV2" ST_MICRO_TVS 128,1034.61 r270 bottom
TVS7 "TVS_ESDAVLC6-1BV2" ST_MICRO_TVS 121,1245 r90 bottom
TVS8 "TVS_ESDAVLC6-1BV2" ST_MICRO_TVS 121,1216.61 r270 bottom
TVS9 "TVS_ESDAVLC6-1BV2" ST_MICRO_TVS 273.86,940.75 r270 bottom
U1 "19.2MHz Oscillator" LCCS165P160X200X70-4N 58,162 r90 top
U2 "Buffer" DSBGA4_.4MM 98,668 r0 top
U3 "LFE3-17EA" BGA328C50P19X19_1000X1000X150 231.26,432.17 r180 top locked
U4 "U_LT3460EDC-1" DFN6 543,777 r90 top
U5 "M25P16-VMC6TG" UFDFN8 241.14,87.6 r270 top
U6 "Buffer" DSBGA4_.4MM 141,668 r0 top
U7 "3.3V STEP UP/DOWN" QFN40P300X300X80_HS-13L 405,1110 r0 top
U11 "TPS82675SIPT" "MICRP SIP" 390,85 r270 top
U12 "2.5V Buck Converter" BGA4C50P2X2_105X138X60 585,220 r270 top
U13 "Power Switch" "DSBGA4 _.5MM" 70,74 r0 top

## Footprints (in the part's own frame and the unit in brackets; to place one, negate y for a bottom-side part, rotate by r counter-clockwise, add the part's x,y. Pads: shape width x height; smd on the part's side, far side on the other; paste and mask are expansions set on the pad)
2-XFDFN [mm] "2-XFDFN"
  rect 0.4x0.7 smd mask+0: 1(0.35,0) 2(-0.35,0)
  silkscreen extent -0.78,-0.38 -0.78,0.4
"8-PIN TEST INTERFACE" [mm] "SOIC, 4-Leads, Body 3.7x6.0mm (max), Pitch 1.27mm, IPC High Density"
  rect 1x0.4 smd mask+0: 1(0,2.1) 2(0,1.5) 3(0,0.9) 4(0,0.3) 5(0,-0.3) 6(0,-0.9) 7(0,-2.1) 8(0,-1.5)
  silkscreen extent -0.11,2.62 0.14,2.87
"10PIN SMD CONNECTOR" [mil] "10PIN TONKA MODULE CONNECTOR"
  oval 75x80 hole 66 mask+0: 1(0,0) 3(90.55,0) 5(181.1,0) 7(271.65,0) 9(362.2,0)
  round 80 hole 66 mask+0: 2(0,90.55) 4(90.55,90.55) 6(181.1,90.55) 8(271.65,90.55)
  round 74.8 hole 66 mask+0: 10(362.2,90.55)
  silkscreen extent -58,-41 417,152, body extent -36,-36 398,127, height 16
BGA4C40P2X2_80X80X40 [mm] "BGA, 4-Leads, Body 0.80x0.80mmx0.40mm, Pitch 0.40mm"
  round 0.205 smd mask+0: 1(-0.2,-0.2) 2(-0.2,0.2) 3(0.2,0.2) 4(0.2,-0.2)
  silkscreen extent -0.6,-0.55 0.4,0.4, body extent -0.4,-0.4 0.4,0.4, height 0.4
BGA4C50P2X2_105X138X60 [mm] "BGA, 4-Leads, Body 1.05x1.38mmx0.60mm, Pitch 0.50mm"
  round 0.275 smd mask+0: A1(-0.433,-0.25) A3(-0.433,0.25) B2(0,0) C1(0.433,-0.25) C3(0.433,0.25)
  silkscreen extent -0.84,-0.68 0.69,0.53, body extent -0.69,-0.52 0.69,0.53, height 0.6
BGA6C50P3X2_145X96X59 [mm] "BGA, 6-Leads, Body 1.45x0.96mmx0.59mm, Pitch 0.50mm"
  round 0.26 smd mask+0: 1(-0.5,-0.25) 2(-0.5,0.25) 3(0,0.25) 4(0.5,0.25) 5(0.5,-0.25) 6(0,-0.25)
  silkscreen extent -0.91,-0.59 0.72,0.48, body extent -0.72,-0.48 0.72,0.48, height 0.59
BGA328C50P19X19_1000X1000X150 [mm] "BGA, 328-Leads, Body 10.00x10.00mmx1.50mm, Pitch 0.50mm"
  round 0.25 smd mask+0: A1(-4.5,4.5) A2(-4,4.5) A3(-3.5,4.5) A4(-3,4.5) A5(-2.5,4.5) A6(-2,4.5) A7(-1.5,4.5) A8(-1,4.5) A9(-0.5,4.5) A10(0,4.5) A11(0.5,4.5) A12(1,4.5) A13(1.5,4.5) A14(2,4.5) A15(2.5,4.5) A16(3,4.5) A17(3.5,4.5) A18(4,4.5) A19(4.5,4.5) B1(-4.5,4) B2(-4,4) B3(-3.5,4) B4(-3,4) B5(-2.5,4) B6(-2,4) B7(-1.5,4) B8(-1,4) B9(-0.5,4) B10(0,4) B11(0.5,4) B12(1,4) B13(1.5,4) B14(2,4) B15(2.5,4) B16(3,4) B17(3.5,4) B18(4,4) B19(4.5,4) C1(-4.5,3.5) C2(-4,3.5) C3(-3.5,3.5) C4(-3,3.5) C5(-2.5,3.5) C6(-2,3.5) C7(-1.5,3.5) C8(-1,3.5) C9(-0.5,3.5) C10(0,3.5) C11(0.5,3.5) C12(1,3.5) C13(1.5,3.5) C14(2,3.5) C15(2.5,3.5) C16(3,3.5) C17(3.5,3.5) C18(4,3.5) C19(4.5,3.5) D1(-4.5,3) D2(-4,3) D3(-3.5,3) D4(-3,3) D16(3,3) D17(3.5,3) D18(4,3) D19(4.5,3) E1(-4.5,2.5) E2(-4,2.5) E3(-3.5,2.5) E4(-3,2.5) E6(-2,2.5) E7(-1.5,2.5) E8(-1,2.5) E9(-0.5,2.5) E10(0,2.5) E11(0.5,2.5) E12(1,2.5) E13(1.5,2.5) E14(2,2.5) E16(3,2.5) E17(3.5,2.5) E18(4,2.5) E19(4.5,2.5) F1(-4.5,2) F2(-4,2) F3(-3.5,2) F4(-3,2) F6(-2,2) F7(-1.5,2) F8(-1,2) F9(-0.5,2) F10(0,2) F11(0.5,2) F12(1,2) F13(1.5,2) F14(2,2) F16(3,2) F17(3.5,2) F18(4,2) F19(4.5,2) G1(-4.5,1.5) G2(-4,1.5) G3(-3.5,1.5) G4(-3,1.5) G6(-2,1.5) G7(-1.5,1.5) G8(-1,1.5) G9(-0.5,1.5) G10(0,1.5) G11(0.5,1.5) G12(1,1.5) G13(1.5,1.5) G14(2,1.5) G16(3,1.5) G17(3.5,1.5) G18(4,1.5) G19(4.5,1.5) H1(-4.5,1) H2(-4,1) H3(-3.5,1) H4(-3,1) H6(-2,1) H7(-1.5,1) H8(-1,1) H9(-0.5,1) H10(0,1) H11(0.5,1) H12(1,1) H13(1.5,1) H14(2,1) H16(3,1) H17(3.5,1) H18(4,1) H19(4.5,1) J1(-4.5,0.5) J2(-4,0.5) J3(-3.5,0.5) J4(-3,0.5) J6(-2,0.5) J7(-1.5,0.5) J8(-1,0.5) J9(-0.5,0.5) J10(0,0.5) J11(0.5,0.5) J12(1,0.5) J13(1.5,0.5) J14(2,0.5) J16(3,0.5) J17(3.5,0.5) J18(4,0.5) J19(4.5,0.5) K1(-4.5,0) K2(-4,0) K3(-3.5,0) K4(-3,0) K6(-2,0) K7(-1.5,0) K8(-1,0) K9(-0.5,0) K10(0,0) K11(0.5,0) K12(1,0) K13(1.5,0) K14(2,0) K16(3,0) K17(3.5,0) K18(4,0) K19(4.5,0) L1(-4.5,-0.5) L2(-4,-0.5) L3(-3.5,-0.5) L4(-3,-0.5) L6(-2,-0.5) L7(-1.5,-0.5) L8(-1,-0.5) L9(-0.5,-0.5) L10(0,-0.5) L11(0.5,-0.5) L12(1,-0.5) L13(1.5,-0.5) L14(2,-0.5) L16(3,-0.5) L17(3.5,-0.5) L18(4,-0.5) L19(4.5,-0.5) M1(-4.5,-1) M2(-4,-1) M3(-3.5,-1) M4(-3,-1) M6(-2,-1) M7(-1.5,-1) M8(-1,-1) M9(-0.5,-1) M10(0,-1) M11(0.5,-1) M12(1,-1) M13(1.5,-1) M14(2,-1) M16(3,-1) M17(3.5,-1) M18(4,-1) M19(4.5,-1) N1(-4.5,-1.5) N2(-4,-1.5) N3(-3.5,-1.5) N4(-3,-1.5) N6(-2,-1.5) N7(-1.5,-1.5) N8(-1,-1.5) N9(-0.5,-1.5) N10(0,-1.5) N11(0.5,-1.5) N12(1,-1.5) N13(1.5,-1.5) N14(2,-1.5) N16(3,-1.5) N17(3.5,-1.5) N18(4,-1.5) N19(4.5,-1.5) P1(-4.5,-2) P2(-4,-2) P3(-3.5,-2) P4(-3,-2) P6(-2,-2) P7(-1.5,-2) P8(-1,-2) P9(-0.5,-2) P10(0,-2) P11(0.5,-2) P12(1,-2) P13(1.5,-2) P14(2,-2) P16(3,-2) P17(3.5,-2) P18(4,-2) P19(4.5,-2) R1(-4.5,-2.5) R2(-4,-2.5) R3(-3.5,-2.5) R4(-3,-2.5) R6(-2,-2.5) R7(-1.5,-2.5) R8(-1,-2.5) R9(-0.5,-2.5) R10(0,-2.5) R11(0.5,-2.5) R12(1,-2.5) R13(1.5,-2.5) R14(2,-2.5) R16(3,-2.5) R17(3.5,-2.5) R18(4,-2.5) R19(4.5,-2.5) T1(-4.5,-3) T2(-4,-3) T3(-3.5,-3) T4(-3,-3) T5(-2.5,-3) T6(-2,-3) T7(-1.5,-3) T8(-1,-3) T9(-0.5,-3) T10(0,-3) T11(0.5,-3) T12(1,-3) T13(1.5,-3) T14(2,-3) T15(2.5,-3) T16(3,-3) T17(3.5,-3) T18(4,-3) T19(4.5,-3) U1(-4.5,-3.5) U2(-4,-3.5) U3(-3.5,-3.5) U4(-3,-3.5) U5(-2.5,-3.5) U6(-2,-3.5) U7(-1.5,-3.5) U8(-1,-3.5) U9(-0.5,-3.5) U10(0,-3.5) U11(0.5,-3.5) U12(1,-3.5) U13(1.5,-3.5) U14(2,-3.5) U15(2.5,-3.5) U16(3,-3.5) U17(3.5,-3.5) U18(4,-3.5) U19(4.5,-3.5) V1(-4.5,-4) V2(-4,-4) V3(-3.5,-4) V4(-3,-4) V5(-2.5,-4) V6(-2,-4) V7(-1.5,-4) V8(-1,-4) V9(-0.5,-4) V10(0,-4) V11(0.5,-4) V12(1,-4) V13(1.5,-4) V14(2,-4) V15(2.5,-4) V16(3,-4) V17(3.5,-4) V18(4,-4) V19(4.5,-4) W1(-4.5,-4.5) W2(-4,-4.5) W3(-3.5,-4.5) W4(-3,-4.5) W5(-2.5,-4.5) W6(-2,-4.5) W7(-1.5,-4.5) W8(-1,-4.5) W9(-0.5,-4.5) W10(0,-4.5) W11(0.5,-4.5) W12(1,-4.5) W13(1.5,-4.5) W14(2,-4.5) W15(2.5,-4.5) W16(3,-4.5) W17(3.5,-4.5) W18(4,-4.5) W19(4.5,-4.5)
  silkscreen extent -5.78,-5 5,5, body extent -5,-5 5,5, height 1.5
C_0402 [mm] "Capacitor 0402"
  rrect50% 0.6x0.65 smd mask+0: 1(-0.5,0) 2(0.5,0)
  silkscreen extent 0,-0.2 0,0.2, body extent -0.5,-0.3 0.5,0.3, height 0.2
C_01005 [mm] "01005 Capacitor"
  rect 0.26x0.22 smd mask+0: 1(-0.23,0) 2(0.23,0)
  silkscreen extent -0.5,-0.25 0.5,0.25, body extent -0.21,-0.11 0.21,0.11, height 0.22
C_ERA-0402 [mm]
  rect 0.5x0.6 smd mask+0: 1(-0.5,0) 2(0.5,0)
  silkscreen extent 0,-0.3 0,0.3, body extent -0.5,-0.3 0.5,0.3, height 0.2
C_ERA-0603 [mm]
  rect 1.1x1 smd mask+0: 1(-0.85,0) 2(0.85,0)
  silkscreen extent -0.64,-0.64 0.64,0.64, body extent -0.8,-0.4 0.8,0.4, height 0.3
C_ERA-0805#1 [mm]
  rect 1.3x1.5 smd mask+0: 1(-0.95,0) 2(0.95,0)
  silkscreen extent -0.64,-0.89 0.64,0.89, body extent -0.94,-0.63 1.06,0.63, height 0.78
C_ERA-0805#2 [mm]
  rect 1.3x1.5 smd: 1(-0.95,0) 2(0.95,0)
  body extent -0.94,-0.62 1.06,0.63, height 0.78
CAPC0201 [mm] "Chip Capacitor, Body 0.6x0.3mm, Height 0.33mm, IPC Medium Density"
  rect 0.46x0.42 smd mask+0: 1(-0.33,0) 2(0.33,0)
  silkscreen extent -0.66,-0.3 0.67,0.3, body extent -0.31,-0.16 0.32,0.17, height 0.33
DFN6 [mm] "QFN, 6-Leads, Body 2.1x2.1mm (max), Pitch 0.50mm, IPC High Density"
  rect 0.25x0.675 smd mask+0: 1(-0.5,-0.91) 2(0,-0.91) 3(0.5,-0.91) 4(0.5,0.91) 5(0,0.91) 6(-0.5,0.91)
  rect 1.42x0.61 smd mask+0: 7(0,0)
  silkscreen extent -1.5,-1.05 1.05,1.05, body extent -1.05,-1.05 1.05,1.05, height 0.8
"DSBGA4 _.5MM" [mm] "BGA, 4-Leads .5MM Pitch"
  round 0.25 smd mask+0: A1(-0.25,0.25) A2(0.25,0.25) B1(-0.25,-0.25) B2(0.25,-0.25)
  silkscreen extent -0.67,-0.5 0.5,0.67, body extent -0.48,-0.48 0.48,0.48, height 0.6
DSBGA4_.4MM [mm] "BGA, 4-Leads"
  round 0.25 smd mask+0: A1(-0.2,-0.2) A2(-0.2,0.2) B1(0.2,-0.2) B2(0.2,0.2)
  silkscreen extent -0.55,-0.55 0.5,0.5, body extent -0.4,-0.4 0.4,0.4, height 0.5
EPM_3X_CONNECTION [mm] "EPM PAD"
  rect 1x0.5 smd mask+0: 0(0,0) 1(0,-1.44) 2(0,-2.88) 3(0,-4.32) 4(0,-5.76)
  rect 0.5x1 smd mask+0: 5(1.422,-6.833)
  body extent 0.66,-8.18 7.57,0.94, height 2.55
L_0806 [mm] "Inductor 0806"
  rrect50% 1.3x1.8 smd mask+0: 1(1,0) 2(-1,0)
  silkscreen extent -0.15,-0.81 0.15,0.79, body extent -1,-0.63 1,0.62, height 0.78
L_SMD_2.2uH [mm] "Inductor"
  rect 1.4x1.7 smd mask+0: 1(1,0) 2(-1,0)
  Component Side region: -0.3,0.85 -0.3,1.7 -0.85,1.7 -1.7,0.85
  Component Side region: 0.3,0.85 0.3,1.7 0.85,1.7 1.7,0.85
  Component Side region: -0.3,-0.85 -0.3,-1.7 -0.85,-1.7 -1.7,-0.85
  Component Side region: 0.3,-0.85 0.3,-1.7 0.85,-1.7 1.7,-0.85
  silkscreen extent -0.15,-1.9 0.15,1.91, body extent -1.7,-1.7 1.7,1.7, height 1.2
LCCS165P160X200X70-4N [mm]
  rect 0.7x0.6 smd mask+0: 1(-0.7,-0.55) 2(0.7,-0.55) 3(0.7,0.55) 4(-0.7,0.55)
  silkscreen extent -1.4,-1.24 1.38,0.87, body extent -1.05,-0.85 1.05,0.85, height 1.2
"MICRP SIP" [mm]
  round 0.3 smd paste+0.02 mask+0: A1(-1,0.8) A2(0,0.8) A3(1,0.8) B1(-1,0) B2(0,0) C1(-1,-0.8) C2(0,-0.8) C3(1,-0.8)
  silkscreen extent -1.8,-1.17 1.48,1.17, body extent -1.48,-1.17 1.48,1.17, height 1
QFN40P300X300X80_HS-13L [mm] "QFN, 12-Leads, Body 3.00x3.00mm, Pitch 0.40mm, Thermal Pad 2.50x1.60mm, IPC High Density"
  rect 0.25x0.5 smd mask+0: 1(-1,-1.275) 2(-0.6,-1.275) 3(-0.2,-1.275) 4(0.2,-1.275) 5(0.6,-1.275) 6(1,-1.275) 7(1,1.275) 8(0.6,1.275) 9(0.2,1.275) 10(-0.2,1.275) 11(-0.6,1.275) 12(-1,1.275)
  rect 2.5x1.6 smd mask+0: 13(0,0)
  silkscreen extent -1.7,-2.16 1.7,1.7, body extent -1.5,-1.5 1.5,1.5, height 0.8
R_0402 [mm] "Resistor 0402"
  rrect50% 0.6x0.65 smd mask+0: 1(-0.5,0) 2(0.5,0)
  silkscreen extent 0,-0.2 0,0.2, body extent -0.51,-0.25 0.51,0.25, height 0.51
R_01005 [mm] "Chip Capacitor, Body 0.4x0.2mm, Height 0.22mm, IPC High Density"
  rect 0.26x0.22 smd mask+0: 1(-0.23,0) 2(0.23,0)
  silkscreen extent -0.5,-0.25 0.5,0.25, body extent -0.21,-0.11 0.21,0.11, height 0.22
RFSHIELD_2X2_MODULE [mm]
  rect 0.254x3 smd mask+0: S(0.15,2.5) S(0.15,6.5) S(0.15,10.5) S(0.15,14.5) S(0.15,18.5) S(0.15,22.5) S(0.15,26.5) S(0.15,30.5) S(0.15,34.5) S(0.15,38.5) S(39.348,2.35) S(39.348,6.35) S(39.348,10.35) S(39.348,14.35) S(39.348,18.35) S(39.348,22.35) S(39.348,26.35) S(39.348,30.35) S(39.348,34.35)
  rect 1x0.254 smd mask+0: S(1.2,40.85) S(15.08,40.85)
  rect 3x0.254 smd mask+0: S(2.5,0.15) S(6.5,0.15) S(10.5,0.15) S(19.5,1.105) S(26.5,0.15) S(30.5,0.15) S(34.5,0.15)
  rect 1.5x0.254 smd mask+0: S(13.421,0.15) S(37.872,0.15)
  rect 2.86x0.254 smd mask+0: S(15.564,1.105)
  rect 1.5x0.454 smd mask+0: S(17.605,39.05) S(37.605,39.05)
  rect 3x0.454 smd mask+0: S(21.605,39.05) S(25.605,39.05) S(29.605,39.05) S(33.605,39.05)
  rect 2.85x0.254 smd mask+0: S(23.577,1.105)
  rect 0.254x1.5 smd mask+0: S(39.333,38.14)
ST_MICRO_TVS [mm] "Chip Capacitor, Body 0.4x0.2mm, Height 0.22mm, IPC High Density"
  rect 0.18x0.225 smd paste-0.225: 1(-0.16,0) 2(0.16,0)
  body extent -0.21,-0.11 0.21,0.11, height 0.22
UFDFN8 [mm]
  rect 1x0.3 smd mask+0: 1(-1.2,1.2) 2(-1.2,0.4) 3(-1.2,-0.4) 4(-1.2,-1.2) 5(1.2,-1.2) 6(1.2,-0.4) 7(1.2,0.4) 8(1.2,1.2)
  rect 0.3x2.4 smd mask+0: 9(0,0)
  silkscreen extent -2.2,-2.2 1.5,2.2, body extent -1.5,-2 1.5,2, height 0.6

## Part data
C1 C2 C3 C4 C5 C6 C7 C12 C13 C14 C15 C17 C18 C19 C20 C21 C22 C23 C24 C25 C26 C27 C28 C29 C30 C32 C33 C34 C35 C36 C39 C44 C51 C58 C62 C63 C64 C65 C66 C67 C68 C69 C70 C71 C73 C83 C84 C85 C86 C87 C88 C89 C90 C94: library part C_01005_0.1uF, "CAP CER 0.1UF 6.3V 20% X5R 01005"
C8 C11 C31 C49 C53: library part C_0805_22µF_35V, "CAP CER 22UF 35V 20% JB 0805"
C9: library part C_0201_0.1UF, "CAP CER 0.1UF 6.3V 10% X5R 0201"
C10: "CAP CER 22PF 50V 5% NP0 0201"
C16 C37: library part C_0402_1.0UF_16V, "CAP CER 1.0UF 16V X5R 0402"
C38 C78: library part C_0805_22UF_6.3V, "CAP CER 22UF 6.3V X7R 10% 0805"
C40 C50 C59 C60 C61 C72 C82: library part C_0402_10uF, "CAP CER 10UF 4V 20% X5R 0402"
C41: library part C_0402_1uF, "CAP CER 1UF 6.3V 20% JB 0402"
C52 C95: library part C_0603_22uF, "CAP CER 22UF 6.3V 20% X5R 0603"
C57 C77: library part C_0201_0.47µF, "CAP CER 0.47UF 6.3V 20% JB 0201"
C81: library part C_0402_4.7uF, "CAP CER 4.7UF 6.3V 10% X7R 0603"
D1 D2 D3 D4: library part D_SBR0240LP-7, "DIODE SUP BARRIER 40V 0.25A 2DFN"
J1: library part J_EPM_3_PAD
J3: library part J_TONKA_MODULE_CONNECTOR
L1: library part L_0805_2.2uH_160mOhm, "INDUCTOR MULTILAYER 2.2UH 0805"
L2: library part L_0806_22uH, "INDUCTOR 22UH 10% 0806 SMD"
L6: library part L_SMD_2.2uH, "COIL CHOKE 2.2UH SHIELDED SMD"
Q1 Q4 Q5 Q6: library part Q_PFET_BGA_30V, "MOSFET P-CH D-S 30V MICROFOOT"
Q2 Q3 Q7 Q8 Q9 Q10 Q11 Q12: library part Q_NFET_BGA_30V, "MOSFET N-CH D-S 30V MICROFOOT"
R1 R5 R6 R15 R31: library part R_01005_1M, "RES 1M OHM 1/32W 1% 01005 SMD"
R2 R9 R20 R21 R59 R60 R61 R62: library part R_01005_1k, "RES 1K OHM 1/32W 1% 01005 SM"
R3 R4 R7 R8 R10 R22 R23 R24 R25 R26 R30 R33 R34 R35 R39 R41 R43 R45: library part R_01005_10K, "RES 10K OHM 1/32W 1% 01005"
R11 R16 R17 R44: library part R_0402_100_5%_PW, "RES 100 OHM 1/5W 5% 0402 SMD"
R12 R18 R19 R58: library part R_0402_270_5%_PW, "RES 270 OHM 1/5W 5% 0402 SMD"
R13: library part R_01005_100K, "RES 100K OHM 1/32W 1% 01005 SMD"
R14 R27 R28 R29 R32: library part R_01005_4.7k, "RES 4.7K OHM 1/32W 1% 01005 SMD"
R52: library part R_01005_33, "RES 33 OHM 1/32W 1% 01005"
S1: library part S_RF_SHIELD_2X2_MODULE
T1: library part TEST_INTERFACE, "8 PIN Test Interface"
TVS1 TVS2 TVS3 TVS4 TVS5 TVS6 TVS7 TVS8 TVS9: "Single Line Bi Trans 8pF"
U1: library part U_ASA-19.200MHZ-L-T, "OSC 19.200 MHZ 3.3V SMD"
U2 U6: library part U_SN74AUP1G34YFPR, "IC BUFFER GATE SGL 4-DSBGA"
U3: library part U_LFE3-17EA-MG328, "IC FPGA 17KLUTS 116I/O 328-BGA"
U4: library part U_LTC3460-1, "IC REG BOOST ADJ 0.18A 6DFN"
U5: library part U_M25P16-VMC6TG, "IC FLASH 16MBIT 75MHZ 8UFDFPN"
U7: library part U_LM3668SD-2833/NOPB, "IC REG BUCK BST SYNC ADJ 12-LLP"
U11: library part U_TPS82675SIPT, "IC REG BUCK SYNC 1.2V 0.6A 8USIP"
U12: library part U_LM3671TL-2.5/NOPB, "IC REG BUCK SYNC 2.5V 0.6A 5USMD"
U13: library part U_TPS22913BYZVT, "IC LOAD SWITCH 5V 4DSBGA"

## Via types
v1: diameter 12, hole 6, Component Side to Solder Side, tented both sides, 444 vias
v2: diameter 12, hole 6, Component Side to Solder Side, 1 vias

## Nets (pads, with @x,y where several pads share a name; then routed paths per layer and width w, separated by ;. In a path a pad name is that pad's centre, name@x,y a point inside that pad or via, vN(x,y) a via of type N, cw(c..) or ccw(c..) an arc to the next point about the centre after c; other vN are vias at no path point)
C_RX_CLK_N: C90.1 J3.6 R8.1 R15.1 TVS8.1 | length 1258.2
  Component Side w4: R15.1@81,1211 95.94,1211 97.95,1213 v1(97.95,1220)
  Solder Side w4: 33.94,1214 34,1214.05 ; R8.1@81,1211 81,1225 ; J3.6@183.31,1184.8 183.31,1196.69 155.5,1224.5 102.45,1224.5 v1(97.95,1220) 92.45,1225.5 45.45,1225.5 34,1214.05 ; C90.1@452,458.06 447.94,458.06 444,462 444,474.97 436.97,482 423,482 414,491 414,517.36 375.36,556 340.97,556 335,561.97 335,617.03 338,620.03 338,656.97 296,698.97 296,725.97 225,796.97 225,865 203.5,886.5 94.5,886.5 45,936 45,1072 52,1079 52,1092 45,1099 45,1111 52,1118 52,1129 45,1136 45,1157 34,1168 34,1214.05
C_RX_CLK_P: C89.1 J3.8 R10.1 R31.1 TVS7.1 | length 1262.2
  Component Side w4: 90.95,1249 R31.1@82,1249 92.95,1249 99.95,1242 v1(100,1242)
  Solder Side w4: R10.1@82,1249 82,1237.56 81.94,1237.5 ; J3.8@183.31,1275.35 183.31,1272.81 147,1236.5 105.5,1236.5 v1(100,1242) 99.95,1242 95.45,1237.5 81.94,1237.5 ; C89.1@429,458.06 432.06,458.06 434,460 434,468 432,470 418.03,470 402,486.03 402,512.38 370.38,544 336,544 323,557 323,622 326,625 326,652 284,694 284,721 213,792 213,860.03 198.53,874.5 89.53,874.5 33,931.03 33,1152.03 22,1163.03 22,1218.92 21.94,1218.97 40.47,1237.5 81.94,1237.5
C_RX_N: C88.1 J3.2 TVS6.1 | length 696.1
  Solder Side w4: J3.2@183.31,1003.7 144.03,1042.97 113,1042.97 98,1027.97 98,1017 105,1010 105,1000 98,993 98,964 123.81,938.2 135,938.2 142.81,946 153.2,946 161,938.2 193.81,938.2 210,922 222,922 230,914 230,902 254,878 254,811 345,720 345,692.97 384,653.97 384,624.05 C88.1@388,620.06
C_RX_P: C87.1 J3.4 TVS5.1 | length 705.2
  Solder Side w4: J3.4@183.31,1094.25 144.03,1054.97 108.03,1054.97 86,1032.94 86,959.03 118.83,926.2 188.83,926.2 242,873.03 242,806.03 333,715.03 333,688 372,649 372,632 ; C87.1@369,620.06 C87.1@372,623.06 ; C87.1@372,623.06 372,632 ; C87.1@372,623.06 372,632
C_TX_CLK_N: C86.1 J3.7 R3.1 R5.1 TVS4.1 | length 1300.6
  Component Side w4: C86.1@467.06,408 471.56,403.5 488.87,403.5 494.37,409 v1(495,409)
  Solder Side w4: J3.7@273.86,1275.35 273.86,1282.86 307,1316 318,1316 347.67,1286.33 347.67,1262 341.61,1255.94 ; R3.1@335,1232.06 342.94,1232.06 ; R5.1@335,1255.94 341.61,1255.94 ; 408.81,744.84 401,752.64 ; v1(495,409) 499,405 506,405 513,412 521,412 528,405 533.03,405 545,416.97 545,425 554,434 562.03,434 569,440.97 569,461 585,477 585,492.38 580.19,497.19 580.19,504.19 585,509 585,518 579,524 579,531 585,537 585,549 578,556 578,564 585,571 585,584 579,590 579,600 585,606 585,626 563,648 540.03,648 496.03,692 482,692 453,721 432.73,721 422.96,730.77 422.88,730.77 401,752.64 ; 341.61,1255.94 348,1249.56 348,1237.11 342.94,1232.06 ; 342.94,1232.06 346.33,1228.67 346.33,1173.7 357.01,1163.01 357.01,1151.99 363,1146 374.03,1146 381,1139.03 381,1130 386.7,1124.3 395.73,1124.3 401,1119.03 401,1094 394,1087 394,1076 401,1069 401,1056 396,1051 396,1038 401,1033 401,752.64
C_TX_CLK_P: C85.1 J3.9 R4.1 R6.1 TVS3.1 | length 1296.9
  Component Side w4: C85.1@467.06,387 471.56,391.5 492.5,391.5 v1(496,388)
  Solder Side w4: J3.9@273.86,1365.9 273.86,1339.14 285,1328 322.97,1328 359.67,1291.3 359.67,1261.33 365.06,1255.94 ; R4.1@369,1232.05 361,1232.05 ; R6.1@371,1255.94 365.06,1255.94 ; 420.81,749.81 413,757.62 ; v1(496,388) 501,393 538,393 581,436 581,456.03 597,472.03 597,630.97 567.97,660 545,660 501,704 486.97,704 457.97,733 437.7,733 427.93,742.77 427.85,742.77 413,757.62 ; 361,1232.05 358,1235.06 358,1248.89 365.06,1255.94 ; 361,1232.05 357.67,1228.72 357.67,1179.33 413,1124 413,757.62
C_TX_N: C84.1 J3.3 TVS2.1 | length 1087.1
  Solder Side w4: J3.3@273.86,1094.25 310.61,1131 323,1131 340,1114 340,1077 333,1070 333,1058 340,1051 340,1039 333,1032 333,1016 340,1009 340,994 332,986 332,968 340,960 340,950 333,943 333,931 340,924 340,913 333,906 333,894 340,887 340,877 351,866 351,849 344,842 344,833 351,826 351,815 345,809 345,801 351,795 351,788 346,783 346,775 351,770 351,765 423,693 440.64,693 524,609.64 524,512 471,459 471,346.97 453.56,329.53 407.53,329.53 C84.1@402.06,335
C_TX_P: C83.1 J3.5 TVS1.1 | length 1086.3
  Solder Side w4: J3.5@273.86,1184.8 273.86,1179.14 310,1143 327.97,1143 352,1118.97 352,881.97 363,870.97 363,769.97 427.97,705 445.62,705 536,614.62 536,507.03 521,492.03 ; C83.1@402.06,315 407.06,320 461,320 481,340 481,452 521,492
CLK_19P2MHZ: R52.2 U3.N18 | length 348.6
  Solder Side w5: 23,214.06 18.93,214.06 ; R52.2@30,214.06 R52.2@30,214.06 18.93,214.06 ; v1(73.7,491.14) 73.7,460.7 58.59,445.59 31.59,445.59 15,429 15,361 26,350 26,263 8.41,245.41 8.41,224.58 18.93,214.06
DETECT_RX: R35.2 U3.B13 | length 575.6
  Inner Layer 1 w5: v1(39,461) 47,461 67.52,440.48 67.52,415.48 98,385 98,327.95 ; 98.98,327.48 106.89,319.57 106.89,308.38 99.57,301.07 99.57,283.43 108.32,274.68 v1(172.2,274.68)
  Solder Side w5: 29,479 29,489 ; v1(39,461) 37,461 29,469 29,489 ; R35.2@150,658.94 150,649 126,625 117,625 109,625 93,609 93,582 75,564 52,564 30,542 29,541 29,489
DONE: R34.1 T1.8 U3.E19 | length 786.8
  Inner Layer 1 w5: 40.52,319.57 40.52,307 ; v1(54.09,333.74) 40.52,320.16 40.52,307 ; v1(211,228) 192,209 83.91,209 40.52,252.39 40.52,307
  Solder Side w5: v1(211,228) 211,218 235,194 245.91,194 310,194 ; 344,194 310,194 ; 559.94,225.94 575,225.94 ; T1.8@593.74,225.94 578,225.94 ; T1.8@604,225.94 578,225.94 ; 310,194 512.86,194 544.8,225.94 575,225.94 ; 575,225.94 578,225.94
EPM_HBA_N: Q3.1 U3.R18 | length 1207.3
  Inner Layer 1 w4: 60.2,544.17 v1(73.78,530.59)
  Inner Layer 1 w5: 60.2,544.17 60.2,555.79 68.11,563.7 73.06,563.7 87.17,577.81 87.17,615.08 105.09,633 125.14,633 134.14,624 197,624 208,635 208,664 217.5,673.5 224.59,673.5 232.5,681.41 232.5,688.5 283.32,739.32 331.32,739.32 356.5,764.5 356.5,784.73 370.27,798.5 428,798.5 434,792.5 447.5,792.5 455.5,800.5 455.5,860.59 472.41,877.5 486.59,877.5 501.5,892.41 501.5,1053.5 453,1102 453,1187 440,1200 422,1200 415,1207 v1(415,1310)
  Solder Side w5: Q3.1@412.13,1338.13 412.13,1312.87 v1(415,1310)
EPM_HBA_P: Q2.1 R59.1 U3.V18 | length 1221.6
  Inner Layer 2 w5: v1(73,590) 73.09,590 86.5,603.41 86.5,614.41 105.09,633 118,633 127,642 127,653.91 165.5,692.41 165.5,716.79 124,758.29 124,871 142.28,889.28 220,889.28 262.72,932 302,932 358,988 358,1303.91 395.09,1341 v1(474,1341)
  Solder Side w5: R59.1@28.54,658.27 28.54,590.46 44.5,574.5 68.5,574.5 73,579 v1(73,590) ; v1(474,1341) 480.87,1347.87 Q2.1@487.13,1347.87
EPM_HBB_N: Q8.1 U3.T17 | length 1141.1
  Inner Layer 1 w5: v1(93,549) 93,550.3 126.57,583.87 126.57,589.52 140.05,603 245,603 257,615 257,675 301.32,719.32 349.68,719.32 402.86,772.5 472.59,772.5 503,802.91 503,865.62 521.5,884.12 521.5,1074.64 492,1104.14 492,1132.91 496.5,1137.41 496.5,1148.98 519.52,1172 519.52,1224.52 v1(575,1280)
  Solder Side w5: Q8.1@567.13,1332.13 567.13,1299.87 575,1292 v1(575,1280)
EPM_HBB_P: Q7.1 R60.1 U3.R17 | length 1488.8
  Inner Layer 1 w5: v1(93.19,530.74) 117.74,530.74 136.57,549.57 136.57,585.38 143.19,592 253,592 268.78,607.78 268.78,667.92 309.86,709 353.5,709 407,762.5 476.73,762.5 513,798.77 513,857 531.5,875.5 531.5,1078.78 502.14,1108.14 502.14,1128.91 506.5,1133.27 506.5,1144.84 529.52,1167.86 529.52,1210.52 618,1299 618,1550 v1(636,1568)
  Solder Side w5: R60.1@621.06,1529 621.06,1548.94 Q7.1@615.87,1554.13 629.13,1554.13 636,1561 v1(636,1568)
EPM_HBC_N: Q11.1 U3.R19 | length 1171.8
  Component Side w5: v1(45,526) 49.59,530.59 53.59,530.59 U3.R19@54.09,530.59
  Inner Layer 2 w5: v1(45,526) 45,543 66,564 115.57,564 127.5,575.93 127.5,602.5 149,624 149,634 149,643.86 200,694.86 200,716 177.78,738.22 164.78,738.22 136,767 136,868.86 146.42,879.28 238,879.28 261.72,903 318,903 397.28,982.28 397.28,1038.72 369.85,1066.15 369.85,1231.85 378,1240 v1(475,1240)
  Solder Side w5: v1(475,1240) 479.13,1244.13 Q11.1@486.13,1244.13
EPM_HBC_P: Q10.1 R61.1 U3.T18 | length 1211.8
  Component Side w5: R61.1@501.06,1295 509.06,1287 v1(515,1287)
  Inner Layer 1 w5: v1(74,549) 74,549.9 73.7,550.2 97.17,573.67 97.17,610.26 108.41,621.5 115,621.5 ; 120.48,621.5 115,621.5 ; 266.42,703.42 274,711 ; 386.59,787.5 385.59,788.5 ; 466,1187 466,1170 ; 492,1090 496,1086 ; v1(515,1287) 509.52,1281.52 509.52,1267 499.52,1257 472.91,1257 461.5,1245.59 461.5,1222.5 466,1218 466,1170 ; 115,621.5 122.5,621.5 130,614 230,614 242.5,626.5 242.5,679.5 274,711 ; 274,711 292.32,729.32 338,729.32 366.5,757.82 366.5,780.59 374.41,788.5 385.59,788.5 ; 385.59,788.5 391.59,782.5 451.64,782.5 465.5,796.36 465.5,829.5 491,855 491,867.77 511.5,888.27 511.5,1070.5 496,1086 ; 466,1170 466,1116 496,1086
  Solder Side w5: Q10.1@501.87,1289.13 512.87,1289.13 v1(515,1287)
EPM_HBD_N: Q12.1 U3.P19 | length 1407.7
  Component Side w5: v1(45,507) 48.91,510.91 U3.P19@54.09,510.91
  Inner Layer 2 w5: v1(45,507) 37,507 31.5,512.5 31.5,605.83 48.5,622.83 55.92,622.83 118.5,685.41 118.5,698.59 123.75,703.84 ; 121.45,701.55 123.75,703.84 ; v1(637,1370) 604.5,1402.5 463.5,1402.5 419,1358 391,1358 340.5,1307.5 340.5,1220.46 343.5,1217.46 343.5,991.5 295,943 259.58,943 215.86,899.28 138.14,899.28 111,872.14 111,757.15 131,737.15 131,711 126.5,706.5 126.41,706.5 123.75,703.84
  Solder Side w5: Q12.1@627.87,1382.13 627.87,1379.13 v1(637,1370)
EPM_HBD_P: Q9.1 R62.1 U3.P17 | length 1183.1
  Component Side w5: v1(535,1311) 539,1315 R62.1@539,1325.94
  Inner Layer 2 w5: v1(93.46,510.91) 137.84,555.28 137.84,569.84 ; 139,571 139,586 159,606 231,606 262,637 262,681.91 229.5,714.41 229.5,842.5 268,881 341,881 433.5,973.5 433.5,992 455,1013.5 455,1047 448.5,1053.5 448.5,1080.5 555,1187 555,1280 565,1290 565,1304.46 552.46,1317 548,1317 541,1317 v1(535,1311)
  Solder Side w5: v1(535,1311) 542.87,1318.87 Q9.1@542.87,1332.13
EPM_REG_EN: R9.1 U3.V19 U4.6 | length 689.8
  Component Side w5: v1(441.43,749) 441.43,754.43 444.36,757.36 451.06,764.06 R9.1@457,764.06 472.94,764.06 479.69,757.31 U4.6@507.17,757.31
  Inner Layer 1 w5: v1(288.95,625.95) 280.5,634.41 280.5,665.5 296.5,681.5 324,681.5 ; 314.41,681.5 324,681.5 ; v1@440,749 v1(441.43,749) 412.91,749 345.41,681.5 324,681.5
  Inner Layer 2 w5: v1(54.09,589.65) 67.74,576 80,576 98,594 98,611.77 109.23,623 126,623 138,635 138,643 ; 138,646.77 138,643 ; v1(179,698) 179,691.77 138,650.77 138,643
  Solder Side w5: v1(179,698) 186.5,705.5 219.59,705.5 232.5,692.59 ; 232.5,690.5 232.5,692.59 ; v1(288.95,625.95) 232.5,682.41 232.5,692.59
EPMA: J1.0 J1.2 J1.4 Q1.4 Q1.5 Q3.4 | length 343.1
  Component Side w15: J1.0@335,1395 357,1395 v1(358,1396) ; J1.2@448.39,1395 455,1395 v1(470,1380) ; v1(539,1381) 553,1395 J1.4@561.77,1395 J1.4@561.5,1394.73
  Solder Side w12: 412,1377 412.13,1376.87 Q3.4@412.13,1353.87
  Solder Side w15: v1(358,1396) 371,1396 382.69,1384.31 ; Q1.4@382.69,1335.16 Q1.5@382.69,1354.84 382.69,1384.31 ; v1(539,1381) 471,1381 v1(470,1380) 467,1377 412,1377 390,1377 382.69,1384.31
EPMB: J1.1 Q5.4 Q5.5 Q8.4 | length 357.9
  Component Side w15: J1.1@391.69,1395 413,1395 v1(415,1397)
  Solder Side w10: 630.69,1460.56 Q5.4@630.69,1477.16 Q5.5@630.69,1496.84
  Solder Side w12: Q8.4@567.13,1347.87 567.13,1395
  Solder Side w15: v1(415,1397) 421,1403 561.13,1403 567.13,1397 ; 566.13,1396 567.13,1395 567.13,1397 ; 630.69,1460.56 567.13,1397
EPMC: J1.3 Q6.4 Q6.5 Q11.4 | length 223.7
  Component Side w15: v1(450,1307) 466.16,1307 505.08,1345.92 J1.3@505.08,1395
  Solder Side w12: Q6.5@449.72,1259.87 Q11.4@486.13,1259.87
  Solder Side w15: Q6.4@449.69,1240.16 Q6.5@449.69,1259.84 449.69,1306.69 v1(450,1307)
EPMD: J1.5 Q4.4 Q4.5 Q12.4 | length 137.2
  Component Side w15: v1(596,1389) 604,1397 J1.5@604,1451
  Solder Side w10: v1(596,1389) 602.87,1382.13 Q12.4@612.13,1382.13 610.16,1380.16 Q4.5@610.16,1349.69 Q4.4@629.84,1349.69
EXO_DETECT_RX: R10.2 U6.A1 | length 731
  Component Side w5: v1(116,718) 118.5,715.5 118.5,699 ; 118.5,703.5 118.5,696 118.5,666.5 124.87,660.13 U6.A1@133.13,660.13
  Inner Layer 1 w5: v1(42.94,1256) 42.94,1243 85,1200.94 85,980 60,955 60,845 41,826 41,745 64,722 112,722 v1(116,718)
  Solder Side w8: v1(42.94,1256) 49.94,1249 R10.2@63.89,1249
EXO_WAKE_RX: R8.2 U2.A1 | length 633.5
  Component Side w8: v1(71.22,663.22) 74.32,660.13 U2.A1@90.13,660.13
  Inner Layer 2 w8: 43,682 43,675 ; 52,666 54.78,663.22 ; v1(64.94,1163) 64.94,1103.94 41,1080 41,980 52,969 52,852 52,714 43,705 43,675 ; v1(71.22,663.22) 54.78,663.22 ; 43,675 54.78,663.22
  Solder Side w8: R8.2@62.89,1211 56.95,1211 49.94,1204 49.94,1189 64.94,1174 v1(64.94,1163)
